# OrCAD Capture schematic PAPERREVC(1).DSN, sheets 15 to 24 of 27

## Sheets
15 PAGE1 (15): size C; title: SNAP, DIGITAL POWER SUPPLIES; block POWER1
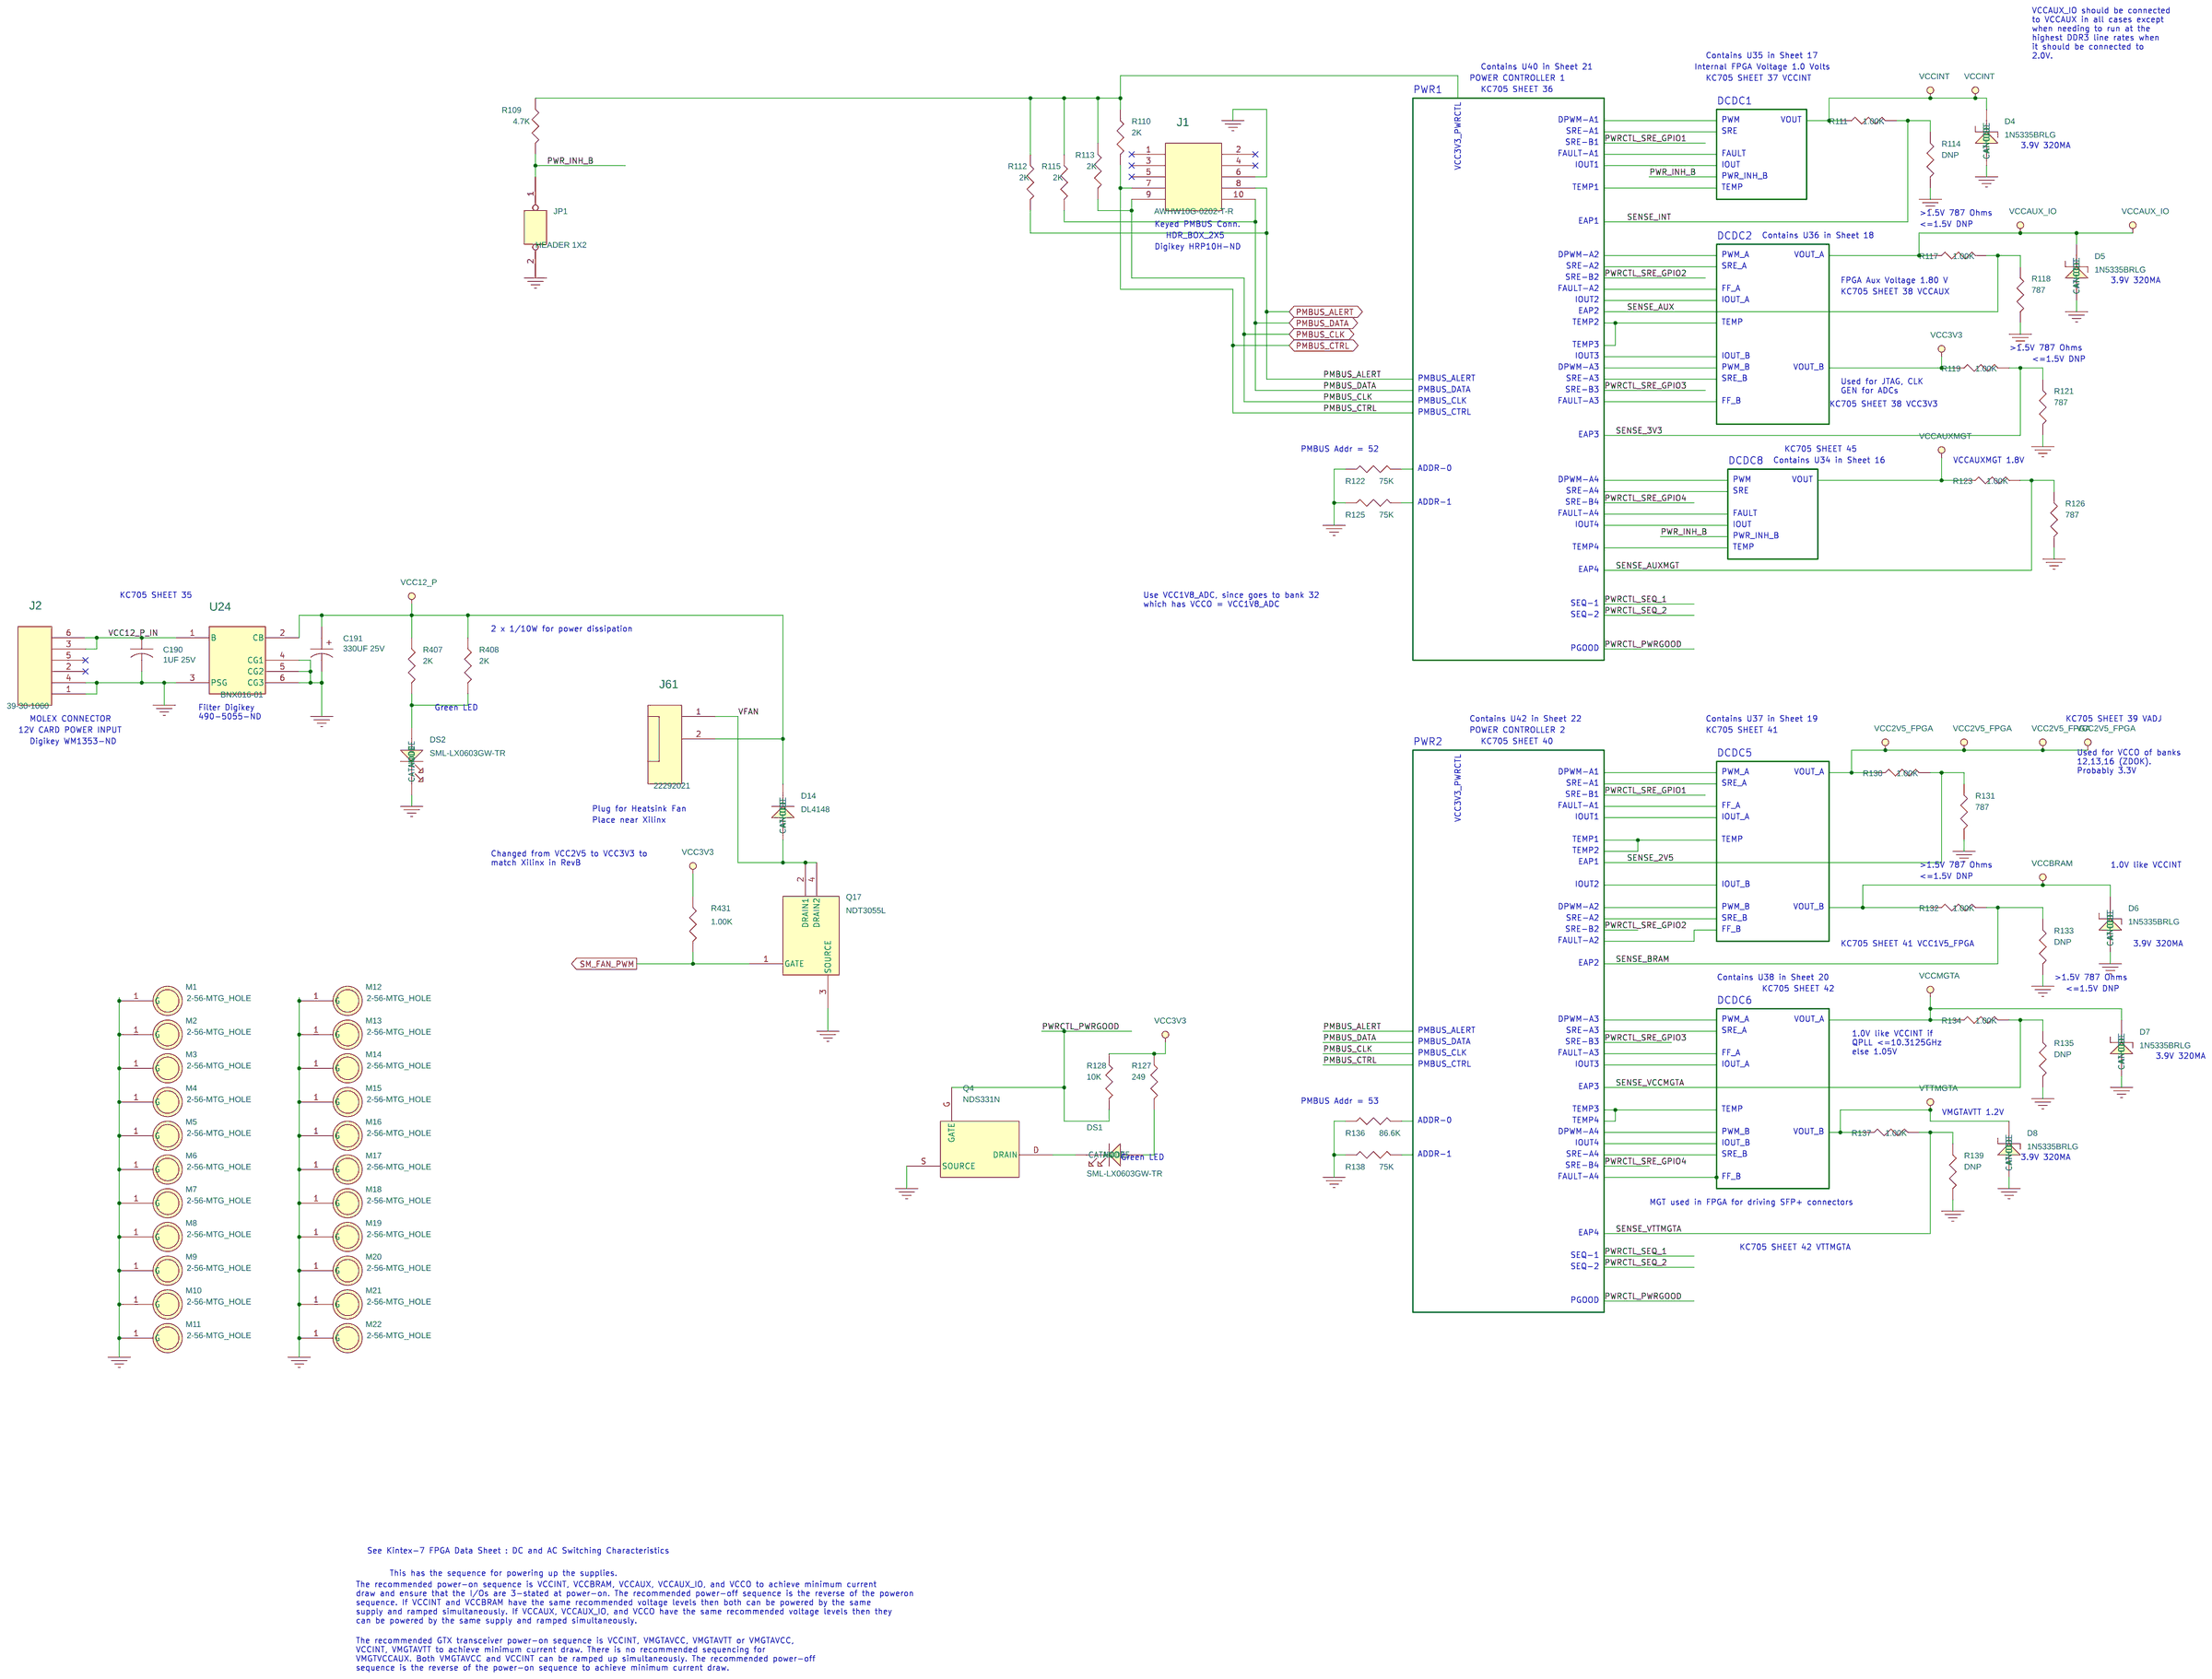
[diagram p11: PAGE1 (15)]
16 PAGE1 (16): size B; title: SNAP, Power1, DCDCx; block POWER1/DCDC6
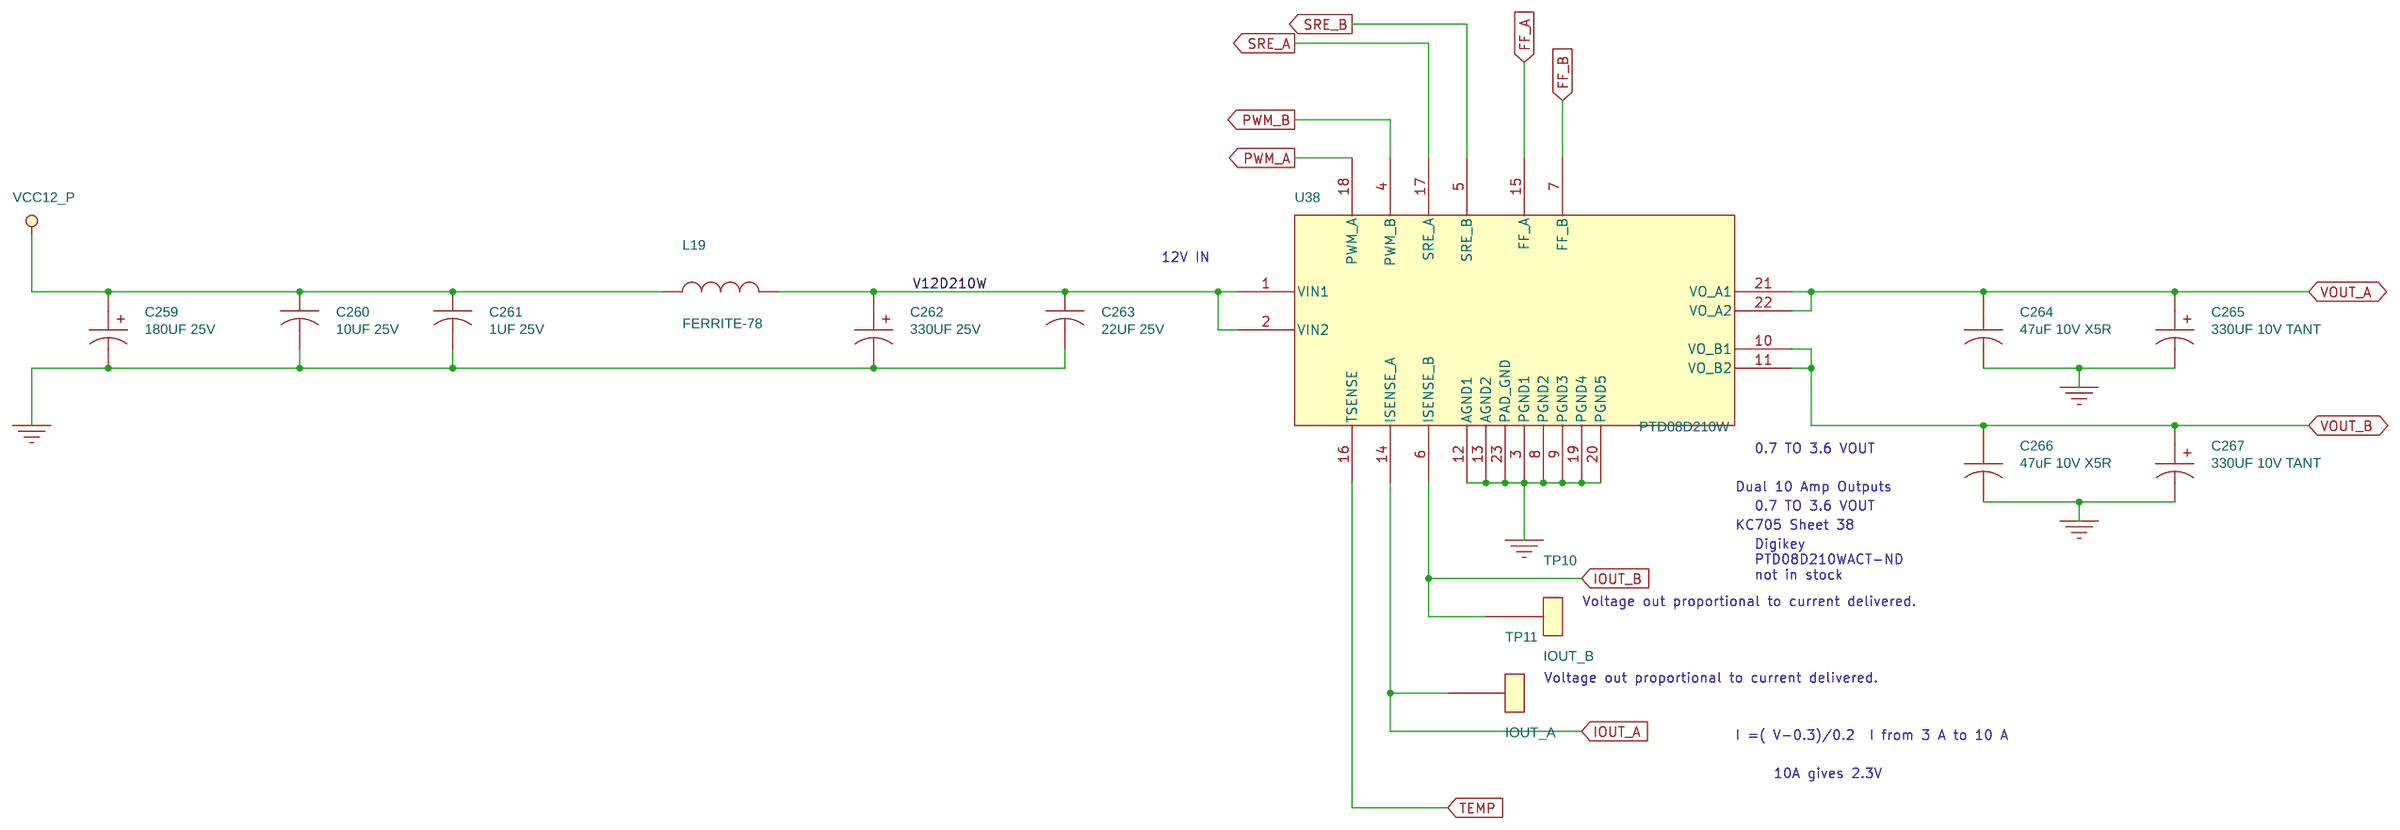
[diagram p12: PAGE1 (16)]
17 PAGE1 (17): size B; title: SNAP, Power1 DCDC1; block POWER1/DCDC1
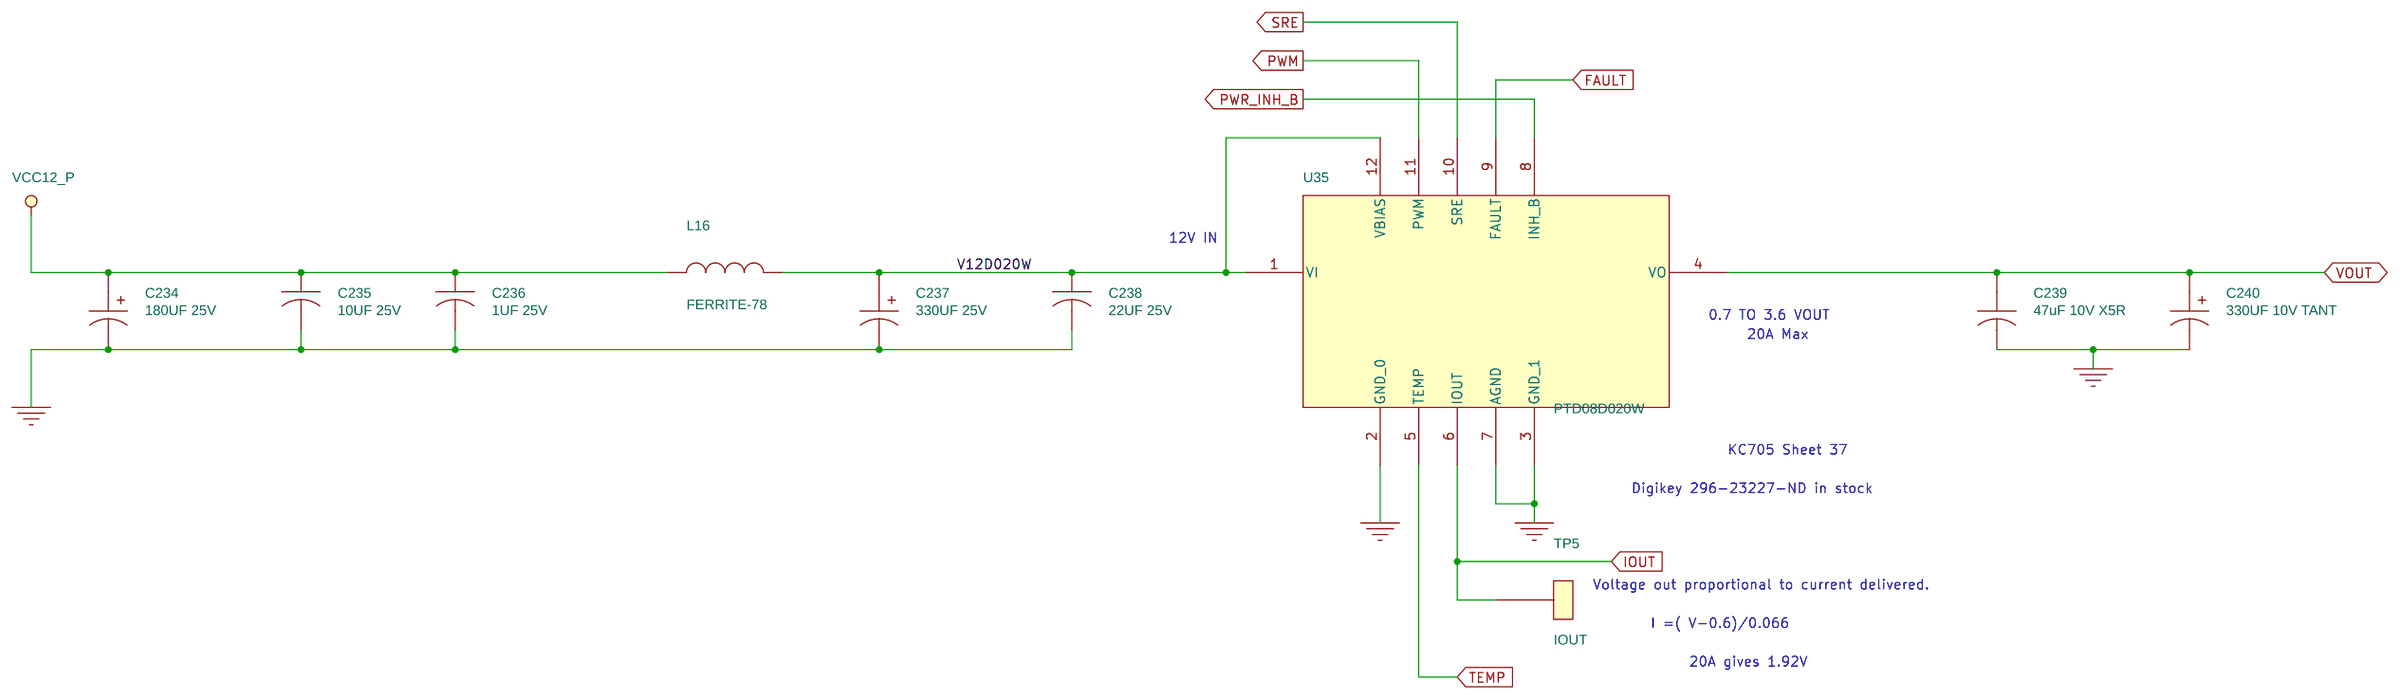
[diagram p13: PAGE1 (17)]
18 PAGE1 (18): block POWER1/DCDC5, another copy of sheet 16
19 PAGE1 (19): size B; title: SNAP, Power1 DCDC8; block POWER1/DCDC8
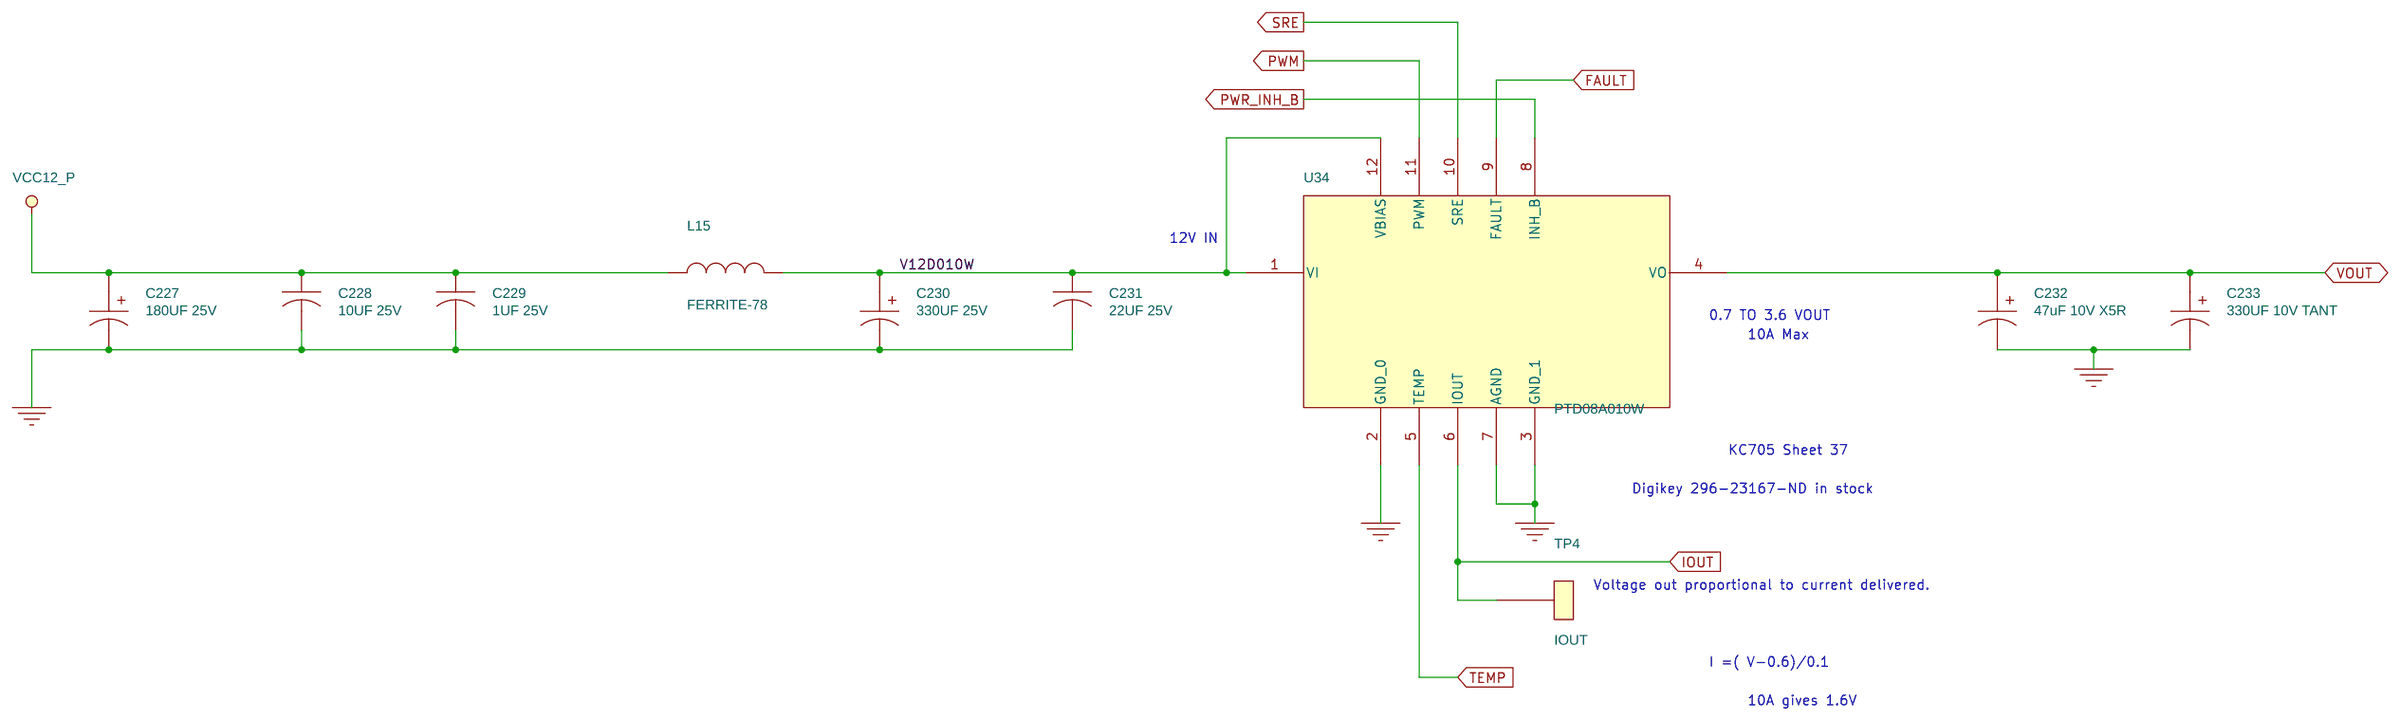
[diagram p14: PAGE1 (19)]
20 PAGE1 (20): size B; title: SNAP, DIGITAL PWM SYSTEM CONTROLLER; block POWER1/PWR1
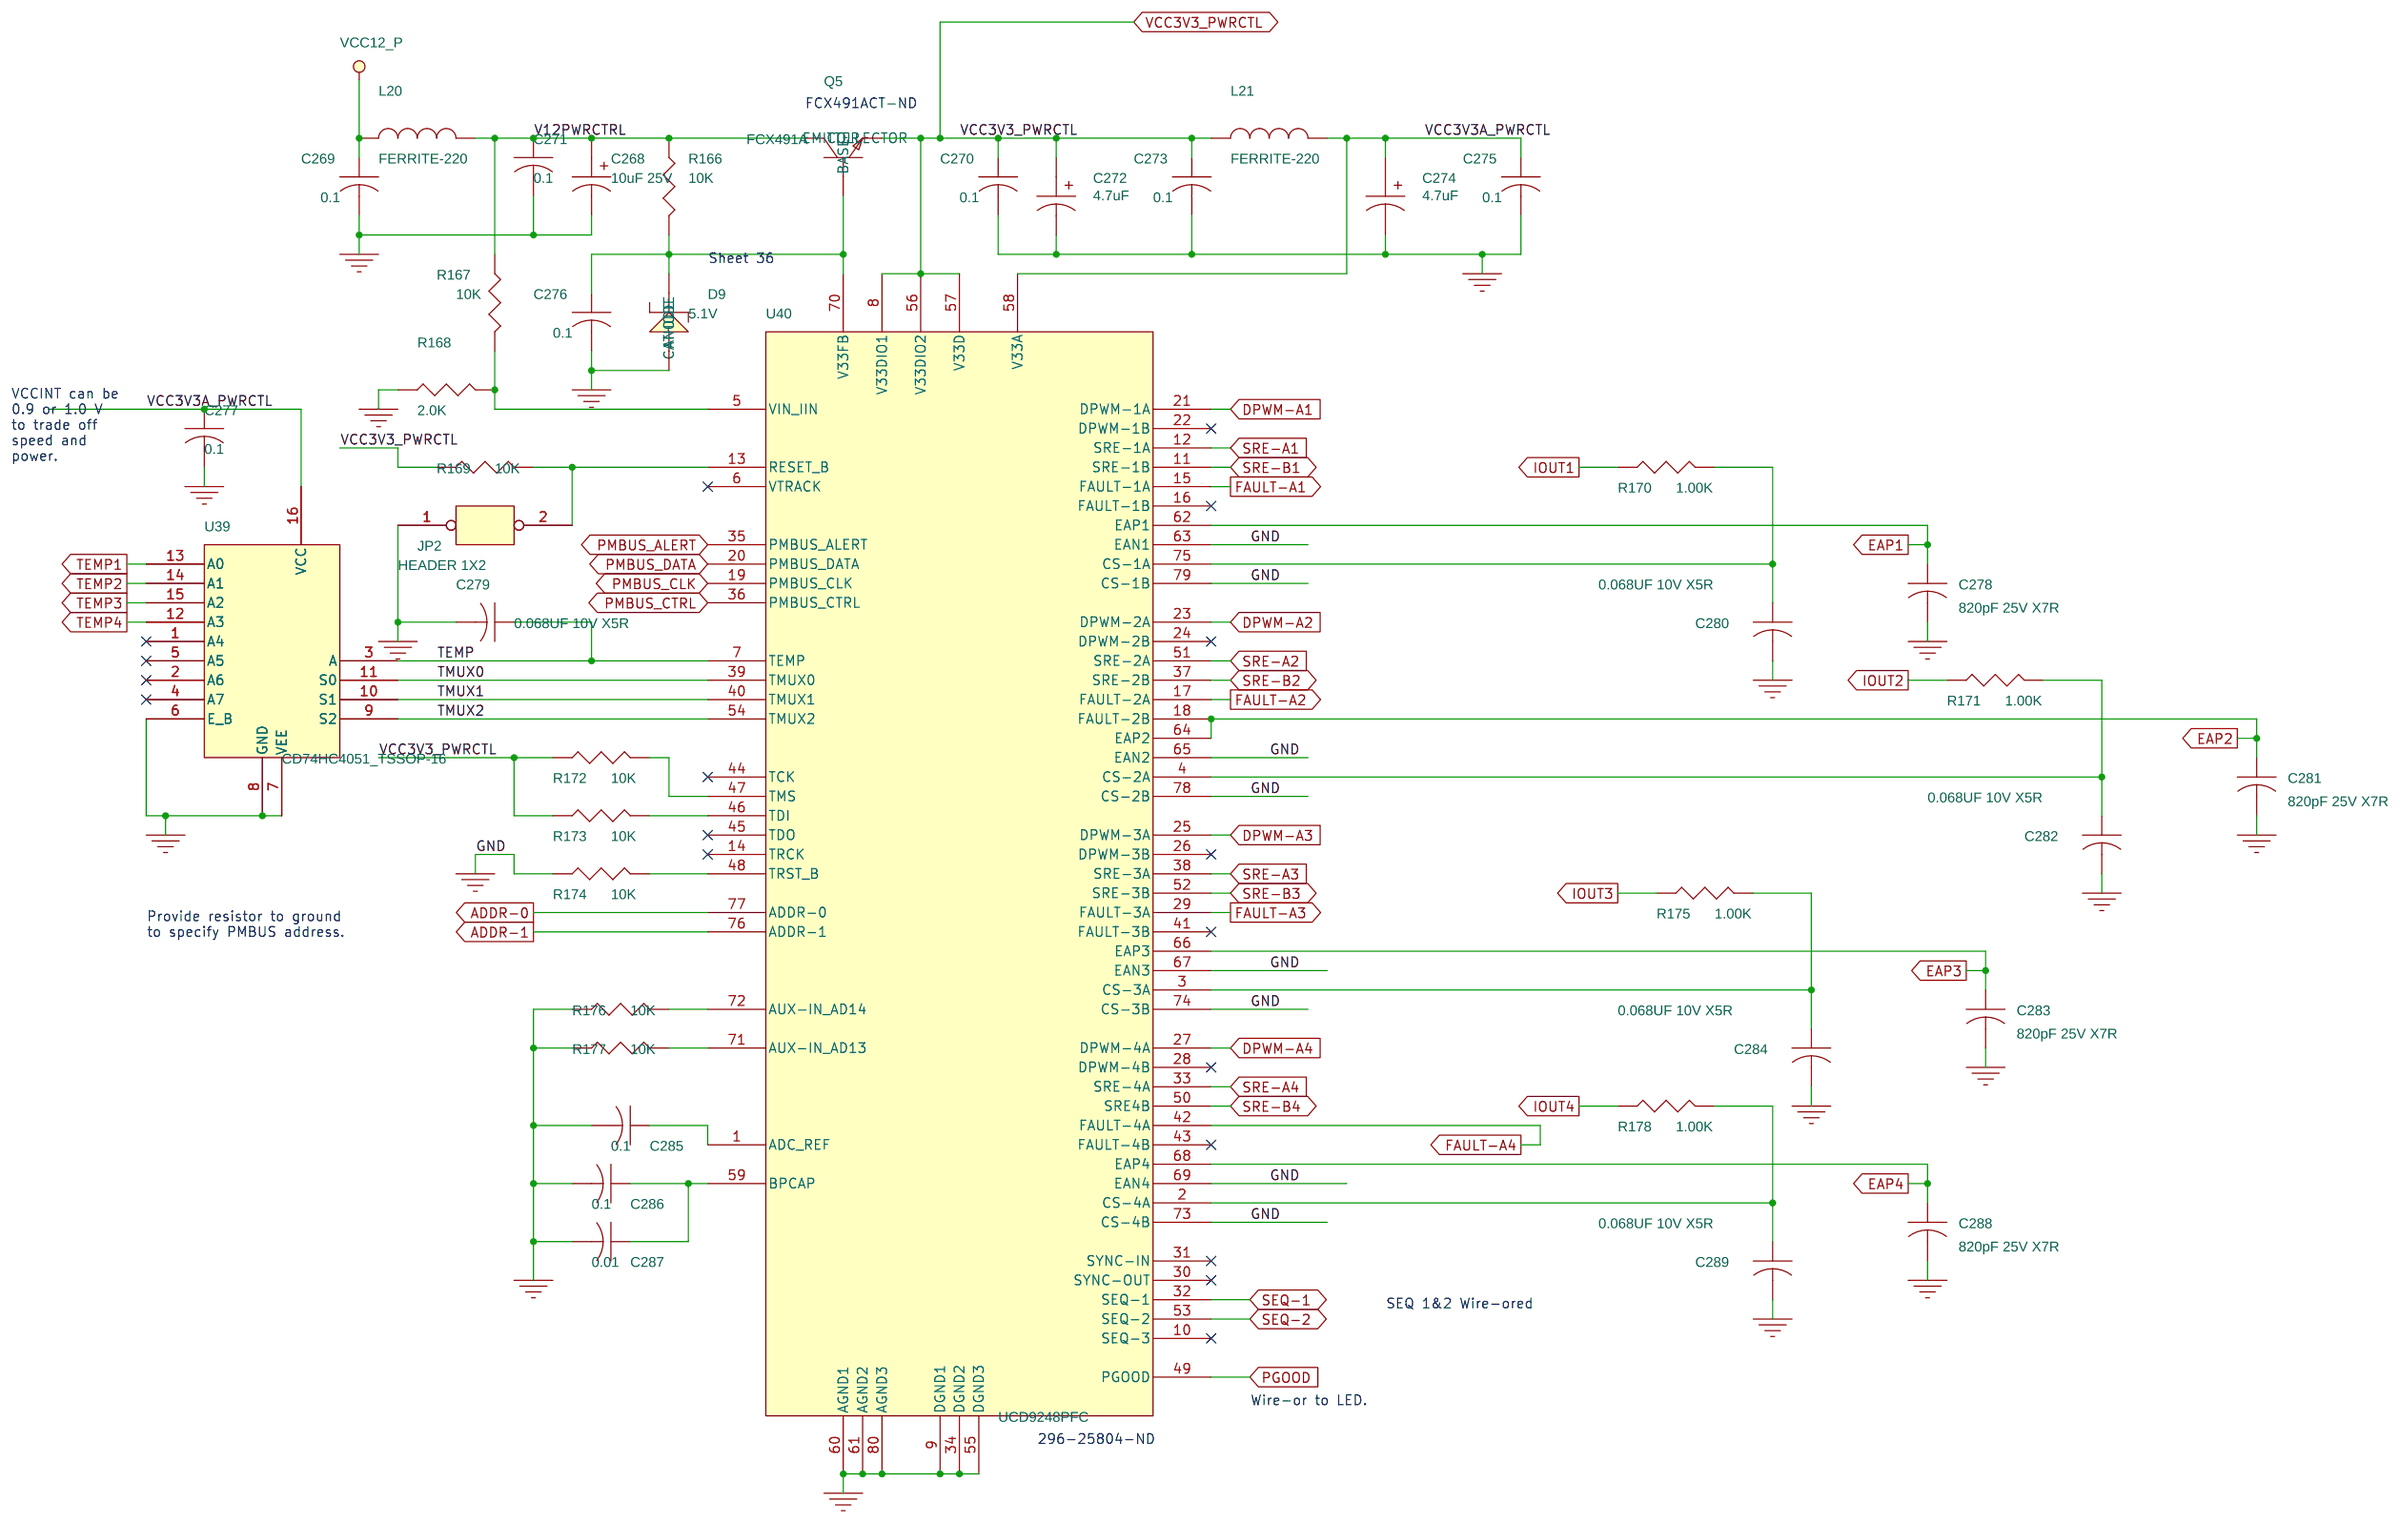
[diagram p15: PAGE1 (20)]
21 PAGE1 (21): block POWER1/PWR2, another copy of sheet 20
22 PAGE1 (22): block POWER1/DCDC2, another copy of sheet 16
23 PAGE1 (23): size B; title: SNAP, Analog Regulators; company: NRAO; block ADCREG
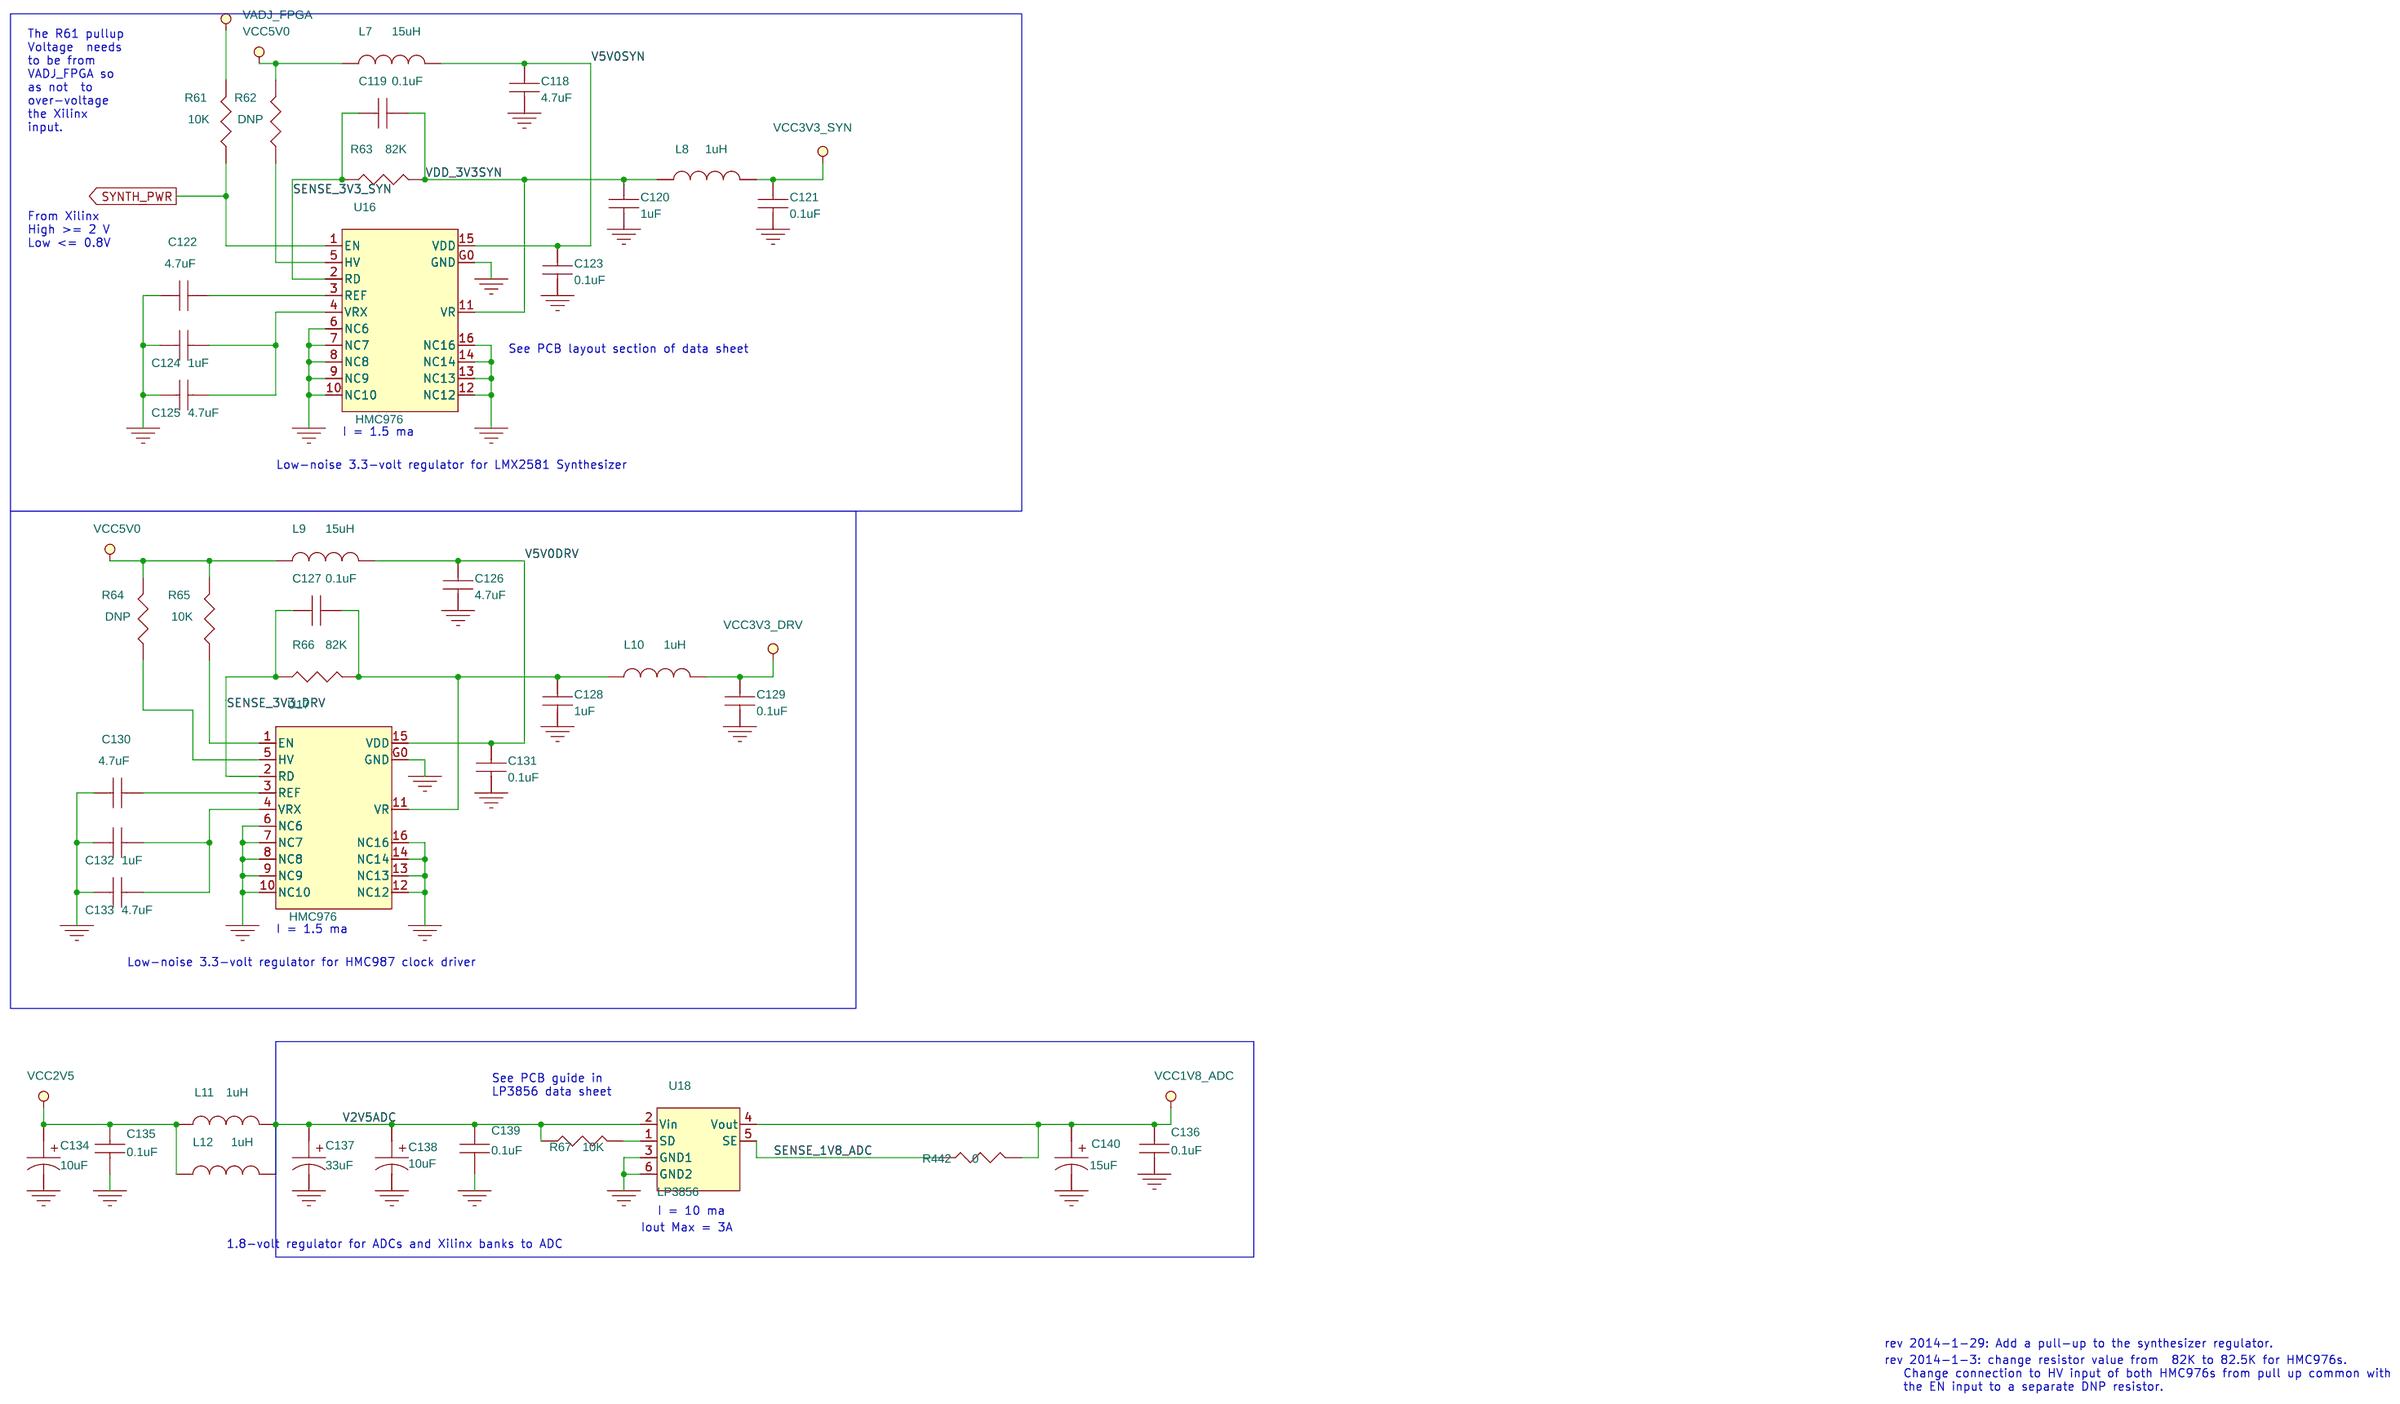
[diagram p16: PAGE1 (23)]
24 PAGE1 (24): size B; title: SNAP, FPGA QSPI; block FPGA14
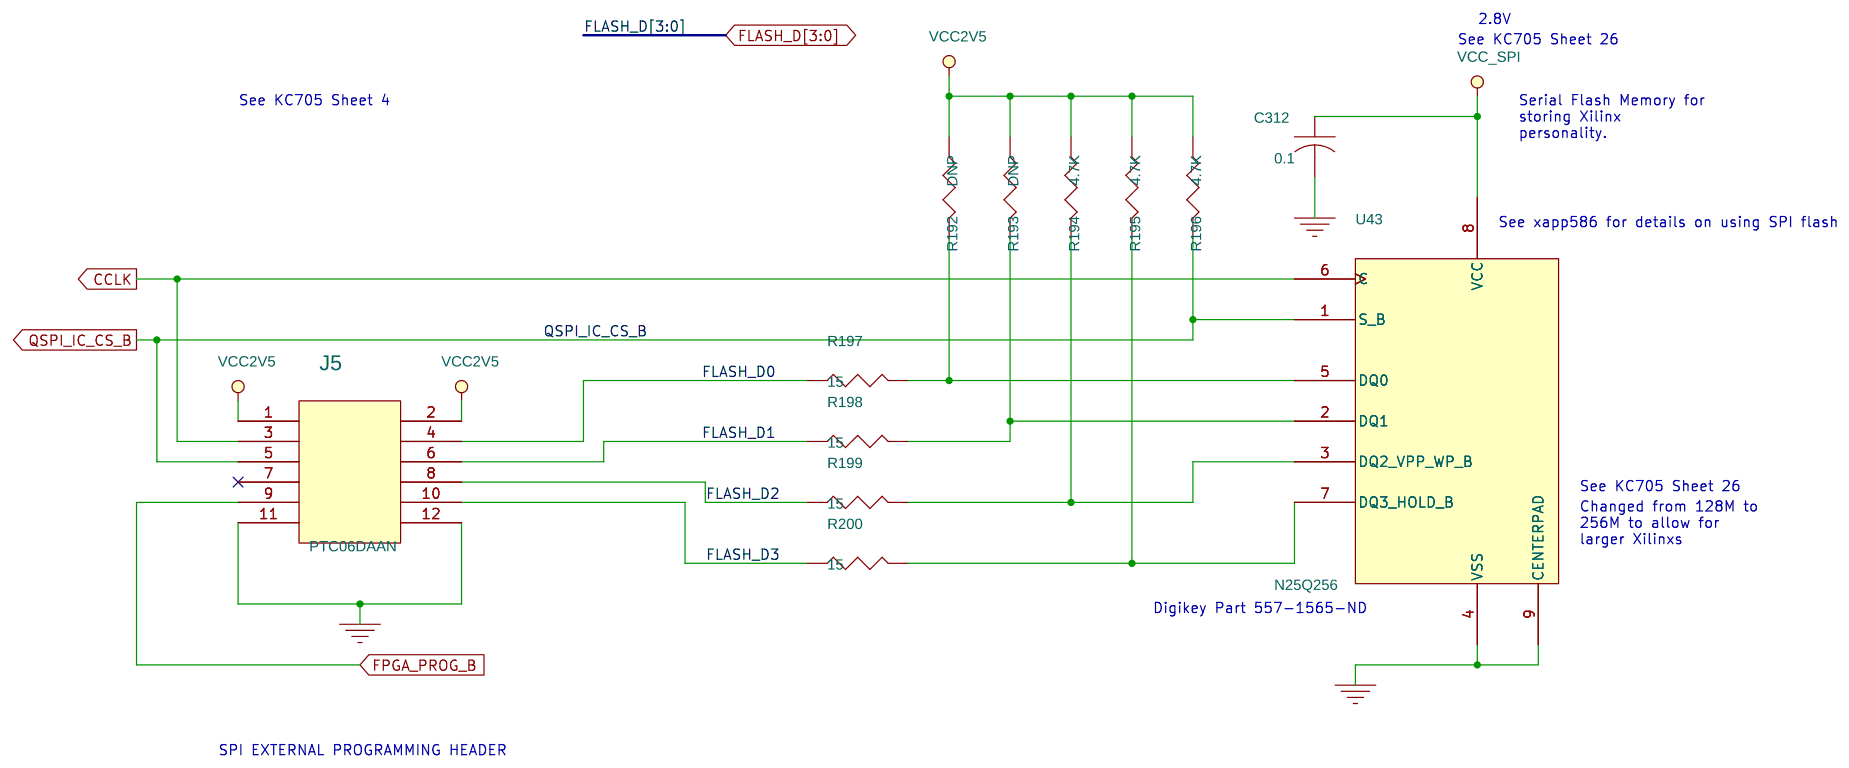
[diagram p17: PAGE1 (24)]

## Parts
sheet PAGE1 (15)
C190  1UF 25V  [CAPC1608X90N]
C191  330UF 25V  [CAPAE830X1050D995DD305L335N]
D4  1N5335BRLG  [DIOAD1365W102L865D350B]
D5  1N5335BRLG  [DIOAD1365W102L865D350B]
D6  1N5335BRLG  [DIOAD1365W102L865D350B]
D7  1N5335BRLG  [DIOAD1365W102L865D350B]
D8  1N5335BRLG  [DIOAD1365W102L865D350B]
D14  DL4148  [DIOMELF3514]
DS1  SML-LX0603GW-TR  [LEDM180X60X60N]
DS2  SML-LX0603GW-TR  [LEDM180X60X60N]
J1  AWHW10G-0202-T-R  [HDRV1016W64P254R2L2032T905H900]
J2  39-30-1060  [MOLEX_39301060]
J61  22292021  [HDR_1x2_LOCK_MOLEX]
JP1  HEADER 1X2  [HDRV254W64P254R1L508T254H838]
M1  2-56-MTG_HOLE  [2-56-MTG_HOLE]
M2  2-56-MTG_HOLE  [2-56-MTG_HOLE]
M3  2-56-MTG_HOLE  [2-56-MTG_HOLE]
M4  2-56-MTG_HOLE  [2-56-MTG_HOLE]
M5  2-56-MTG_HOLE  [2-56-MTG_HOLE]
M6  2-56-MTG_HOLE  [2-56-MTG_HOLE]
M7  2-56-MTG_HOLE  [2-56-MTG_HOLE]
M8  2-56-MTG_HOLE  [2-56-MTG_HOLE]
M9  2-56-MTG_HOLE  [2-56-MTG_HOLE]
M10  2-56-MTG_HOLE  [2-56-MTG_HOLE]
M11  2-56-MTG_HOLE  [2-56-MTG_HOLE]
M12  2-56-MTG_HOLE  [2-56-MTG_HOLE]
M13  2-56-MTG_HOLE  [2-56-MTG_HOLE]
M14  2-56-MTG_HOLE  [2-56-MTG_HOLE]
M15  2-56-MTG_HOLE  [2-56-MTG_HOLE]
M16  2-56-MTG_HOLE  [2-56-MTG_HOLE]
M17  2-56-MTG_HOLE  [2-56-MTG_HOLE]
M18  2-56-MTG_HOLE  [2-56-MTG_HOLE]
M19  2-56-MTG_HOLE  [2-56-MTG_HOLE]
M20  2-56-MTG_HOLE  [2-56-MTG_HOLE]
M21  2-56-MTG_HOLE  [2-56-MTG_HOLE]
M22  2-56-MTG_HOLE  [2-56-MTG_HOLE]
Q4  NDS331N  [SOT95P237X100-4]
Q17  NDT3055L  [SOT230P700x180-4L050N]
R109  4.7K  [RESC1005X35N]
R110  2K  [RESC1005X35N]
R111  1.00K  [RESC1005X35N]
R112  2K  [RESC1005X35N]
R113  2K  [RESC1005X35N]
R114  DNP  [RESC1005X35N]
R115  2K  [RESC1005X35N]
R117  1.00K  [RESC1005X35N]
R118  787  [RESC1005X35N]
R119  1.00K  [RESC1005X35N]
R121  787  [RESC1005X35N]
R122  75K  [RESC1005X35N]
R123  1.00K  [RESC1005X35N]
R125  75K  [RESC1005X35N]
R126  787  [RESC1005X35N]
R127  249  [RESC1005X35N]
R128  10K  [RESC1005X35N]
R130  1.00K  [RESC1005X35N]
R131  787  [RESC1005X35N]
R132  1.00K  [RESC1005X35N]
R133  DNP  [RESC1005X35N]
R134  1.00K  [RESC1005X35N]
R135  DNP  [RESC1005X35N]
R136  86.6K  [RESC1005X35N]
R137  1.00K  [RESC1005X35N]
R138  75K  [RESC1005X35N]
R139  DNP  [RESC1005X35N]
R407  2K  [RESC1005X35N]
R408  2K  [RESC1005X35N]
R431  1.00K  [RESC1005X35N]
U24  BNX016-01  [FIL_BNX01x]
sheet PAGE1 (16)
C259  180UF 25V  [CAPPRD350W60D820H1170P]
C260  10UF 25V  [CAPC3216X180N]
C261  1UF 25V  [CAPC1608X90N]
C262  330UF 25V  [CAPAE830X1050D995DD305L335N]
C263  22UF 25V  [CAPC3216X180N]
C264  47uF 10V X5R  [CAPC3216X180N]
C265  330UF 10V TANT  [CAPMP7343X310N-ALT1]
C266  47uF 10V X5R  [CAPC3216X180N]
C267  330UF 10V TANT  [CAPMP7343X310N-ALT1]
L19  FERRITE-78  [INDM9630X305N]
TP10  IOUT_B  [TP107]
TP11  IOUT_A  [TP107]
U38  PTD08D210W  [DCDC-CONV_PTD08D210W-22N]
sheet PAGE1 (17)
C234  180UF 25V  [CAPPRD350W60D820H1170P]
C235  10UF 25V  [CAPC3216X180N]
C236  1UF 25V  [CAPC1608X90N]
C237  330UF 25V  [CAPAE830X1050D995DD305L335N]
C238  22UF 25V  [CAPC3216X180N]
C239  47uF 10V X5R  [CAPC3216X180N]
C240  330UF 10V TANT  [CAPMP7343X310N-ALT1]
L16  FERRITE-78  [INDM9630X305N]
TP5  IOUT  [TP107]
U35  PTD08D020W  [DCDC-CONV_PTD08A020WAD-12N]
sheet PAGE1 (18)
C250  180UF 25V  [CAPPRD350W60D820H1170P]
C251  10UF 25V  [CAPC3216X180N]
C252  1UF 25V  [CAPC1608X90N]
C253  330UF 25V  [CAPAE830X1050D995DD305L335N]
C254  22UF 25V  [CAPC3216X180N]
C255  47uF 10V X5R  [CAPC3216X180N]
C256  330UF 10V TANT  [CAPMP7343X310N-ALT1]
C257  47uF 10V X5R  [CAPC3216X180N]
C258  330UF 10V TANT  [CAPMP7343X310N-ALT1]
L18  FERRITE-78  [INDM9630X305N]
TP8  IOUT_B  [TP107]
TP9  IOUT_A  [TP107]
U37  PTD08D210W  [DCDC-CONV_PTD08D210W-22N]
sheet PAGE1 (19)
C227  180UF 25V  [CAPPRD350W60D820H1170P]
C228  10UF 25V  [CAPC3216X180N]
C229  1UF 25V  [CAPC1608X90N]
C230  330UF 25V  [CAPAE830X1050D995DD305L335N]
C231  22UF 25V  [CAPC3216X180N]
C232  47uF 10V X5R  [CAPC3216X180N]
C233  330UF 10V TANT  [CAPMP7343X310N-ALT1]
L15  FERRITE-78  [INDM9630X305N]
TP4  IOUT  [TP107]
U34  PTD08A010W  [DCDC-CONV_PTD08A010WAD-12N]
sheet PAGE1 (20)
C268  10uF 25V  [CAPC3216X180N]
C269  0.1  [CAPC1005X50L]
C270  0.1  [CAPC1005X50L]
C271  0.1  [CAPC1005X50L]
C272  4.7uF  [CAPC2012X140N]
C273  0.1  [CAPC1005X50L]
C274  4.7uF  [CAPC2012X140N]
C275  0.1  [CAPC1005X50L]
C276  0.1  [CAPC1005X50L]
C277  0.1  [CAPC1005X50L]
C278  820pF 25V X7R  [CAPC0603X30L]
C279  0.068UF 10V X5R  [CAPC1005X50L]
C280  0.068UF 10V X5R  [CAPC1005X50L]
C281  820pF 25V X7R  [CAPC0603X30L]
C282  0.068UF 10V X5R  [CAPC1005X50L]
C283  820pF 25V X7R  [CAPC0603X30L]
C284  0.068UF 10V X5R  [CAPC1005X50L]
C285  0.1  [CAPC1005X50L]
C286  0.1  [CAPC1005X50L]
C287  0.01  [CAPC1005X50L]
C288  820pF 25V X7R  [CAPC0603X30L]
C289  0.068UF 10V X5R  [CAPC1005X50L]
D9  5.1V  [SOD3717X135]
JP2  HEADER 1X2  [HDRV254W64P254R1L508T254H838]
L20  FERRITE-220  [INDC1608X95L-ALT1]
L21  FERRITE-220  [INDC1608X95L-ALT1]
Q5  FCX491A  [SOT89]
R166  10K  [RESC1005X35N]
R167  10K  [RESC1005X35N]
R168  2.0K  [RESC1005X35N]
R169  10K  [RESC1005X35N]
R170  1.00K  [RESC1005X35N]
R171  1.00K  [RESC1005X35N]
R172  10K  [RESC1005X35N]
R173  10K  [RESC1005X35N]
R174  10K  [RESC1005X35N]
R175  1.00K  [RESC1005X35N]
R176  10K  [RESC1005X35N]
R177  10K  [RESC1005X35N]
R178  1.00K  [RESC1005X35N]
U39  CD74HC4051_TSSOP-16  [SOP65P640X120-16N]
U40  UCD9248PFC  [QFP50P1400X1400X100-80N]
sheet PAGE1 (21)
C290  10uF 25V  [CAPC3216X180N]
C291  0.1  [CAPC1005X50L]
C292  0.1  [CAPC1005X50L]
C293  0.1  [CAPC1005X50L]
C294  4.7uF  [CAPC2012X140N]
C295  0.1  [CAPC1005X50L]
C296  4.7uF  [CAPC2012X140N]
C297  0.1  [CAPC1005X50L]
C298  0.1  [CAPC1005X50L]
C299  0.1  [CAPC1005X50L]
C300  820pF 25V X7R  [CAPC0603X30L]
C301  0.068UF 10V X5R  [CAPC1005X50L]
C302  0.068UF 10V X5R  [CAPC1005X50L]
C303  820pF 25V X7R  [CAPC0603X30L]
C304  0.068UF 10V X5R  [CAPC1005X50L]
C305  820pF 25V X7R  [CAPC0603X30L]
C306  0.068UF 10V X5R  [CAPC1005X50L]
C307  0.1  [CAPC1005X50L]
C308  0.1  [CAPC1005X50L]
C309  0.01  [CAPC1005X50L]
C310  820pF 25V X7R  [CAPC0603X30L]
C311  0.068UF 10V X5R  [CAPC1005X50L]
D10  5.1V  [SOD3717X135]
JP3  HEADER 1X2  [HDRV254W64P254R1L508T254H838]
L22  FERRITE-220  [INDC1608X95L-ALT1]
L23  FERRITE-220  [INDC1608X95L-ALT1]
Q6  FCX491A  [SOT89]
R179  10K  [RESC1005X35N]
R180  10K  [RESC1005X35N]
R181  2.0K  [RESC1005X35N]
R182  10K  [RESC1005X35N]
R183  1.00K  [RESC1005X35N]
R184  1.00K  [RESC1005X35N]
R185  10K  [RESC1005X35N]
R186  10K  [RESC1005X35N]
R187  10K  [RESC1005X35N]
R188  1.00K  [RESC1005X35N]
R189  10K  [RESC1005X35N]
R190  10K  [RESC1005X35N]
R191  1.00K  [RESC1005X35N]
U41  CD74HC4051_TSSOP-16  [SOP65P640X120-16N]
U42  UCD9248PFC  [QFP50P1400X1400X100-80N]
sheet PAGE1 (22)
C241  180UF 25V  [CAPPRD350W60D820H1170P]
C242  10UF 25V  [CAPC3216X180N]
C243  1UF 25V  [CAPC1608X90N]
C244  330UF 25V  [CAPAE830X1050D995DD305L335N]
C245  22UF 25V  [CAPC3216X180N]
C246  47uF 10V X5R  [CAPC3216X180N]
C247  330UF 10V TANT  [CAPMP7343X310N-ALT1]
C248  47uF 10V X5R  [CAPC3216X180N]
C249  330UF 10V TANT  [CAPMP7343X310N-ALT1]
L17  FERRITE-78  [INDM9630X305N]
TP6  IOUT_B  [TP107]
TP7  IOUT_A  [TP107]
U36  PTD08D210W  [DCDC-CONV_PTD08D210W-22N]
sheet PAGE1 (23)
C118  4.7uF  [CAPC2012X140N]
C119  0.1uF  [CAPC1005X50L]
C120  1uF  [CAPC1608X90N]
C121  0.1uF  [CAPC1005X50L]
C122  4.7uF  [CAPC2012X140N]
C123  0.1uF  [CAPC1005X50L]
C124  1uF  [CAPC1608X90N]
C125  4.7uF  [CAPC2012X140N]
C126  4.7uF  [CAPC2012X140N]
C127  0.1uF  [CAPC1005X50L]
C128  1uF  [CAPC1608X90N]
C129  0.1uF  [CAPC1005X50L]
C130  4.7uF  [CAPC2012X140N]
C131  0.1uF  [CAPC1005X50L]
C132  1uF  [CAPC1608X90N]
C133  4.7uF  [CAPC2012X140N]
C134  10uF  [CAPC3216X180N]
C135  0.1uF  [CAPC1005X50L]
C136  0.1uF  [CAPC1005X50L]
C137  33uF  [CAPMP7343X310N-ALT1]
C138  10uF  [CAPC3216X180N]
C139  0.1uF  [CAPC1005X50L]
C140  15uF  [CAPC1608X90N]
L7  15uH  [INDM4532X340N]
L8  1uH  [INDM4532X340N]
L9  15uH  [INDM4532X340N]
L10  1uH  [INDM4532X340N]
L11  1uH  [INDM4532X340N]
L12  1uH  [INDM4532X340N]
R61  10K  [RESC1005X35N]
R62  DNP  [RESC1005X35N]
R63  82K  [RESC1005X35N]
R64  DNP  [RESC1005X35N]
R65  10K  [RESC1005X35N]
R66  82K  [RESC1005X35N]
R67  10K  [RESC1005X35N]
R442  0  [RESC1005X35N]
U16  HMC976  [QFN50P300X300X100-17T178X178L]
U17  HMC976  [QFN50P300X300X100-17T178X178L]
U18  LP3856  [TO170P1430X470-6N-ALT1]
sheet PAGE1 (24)
C312  0.1  [CAPC1005X50L]
J5  PTC06DAAN  [HDRV6X2]
R192  DNP  [RESC1608X50N]
R193  DNP  [RESC1608X50N]
R194  4.7K  [RESC1005X35N]
R195  4.7K  [RESC1005X35N]
R196  4.7K  [RESC1005X35N]
R197  15  [RESC1005X35N]
R198  15  [RESC1005X35N]
R199  15  [RESC1005X35N]
R200  15  [RESC1005X35N]
U43  N25Q256  [DFN127P600X800X100-9T526X490N]

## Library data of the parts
C190 C228 C229 C231 C235 C236 C238 C242 C243 C245 C251 C252 C254 C260 C261 C263 C269-C271 C273 C275-C289 C291-C293 C295 C297-C312 = CAP_0
C191 C227 C230 C232-C234 C237 C240 C241 C244 C247 C249 C250 C253 C256 C258 C259 C262 C265 C267 C272 C274 C294 C296 = CAPACITOR_POL_0
D4-D8 = DIODE_ZENER_1
D14 = DIODE_0
DS1 = LED_3
DS2 = LED_2
J1 = HEADER_6x2_SM_14: COMPHEIGHT: 0.000; DECOUPLER: NO; MEMORY: NO
J2 = HEADER_6x2_SM_15: COMPHEIGHT: 0.000; DECOUPLER: NO; MEMORY: NO
J61 = HEADER_6x2_SM_21: COMPHEIGHT: 0.000; DECOUPLER: NO; MEMORY: NO
JP1 = HEADER_2X2_3
M1-M22 = 2-56-MTG-HOLE_0: Designator: <Designator>
Q4 = XC17256L_14
Q17 = XC17256L_30
R109 R114 R118 R121 R122 R125-R128 R131 R133 R135 R136 R138 R139 R166-R191 R431 = RESISTOR_0: COMPHEIGHT: 0.000; DECOUPLER: NO; MEMORY: NO; POWER: 1/10W; PRECISION: 1%
R110-R113 R115 R117 R119 R123 R130 R132 R134 R137 R407 R408 R442 = RESISTOR_0: COMPHEIGHT: 0.000; DECOUPLER: NO; MEMORY: NO; POWER: 1/16W; PRECISION: 1%
U24 = HEADER_6x2_SM_18: COMPHEIGHT: 0.000; DECOUPLER: NO; MEMORY: NO
C246 C255 C264 = CAPACITOR_POL_4
C248 C257 C266 = CAPACITOR_POL_5
L15-L23 = INDUCTOR_0
TP4-TP11 = TEST_POINT
U36-U38 = 1_2_BRICK_23: COMPFIXED: NO; COMPGROUP: 0; COMPHEIGHT: 0.000; COMPKEY: NO; COMPLOC: [9600.000,-13400.000]; COMPLOCKED: NO; COMPROT: 0; COMPSIDE: TOP; DECOUPLER: NO; MEMORY: NO
C239 = CAPACITOR_POL_3
U35 = 1_2_BRICK_24: COMPFIXED: NO; COMPGROUP: 0; COMPHEIGHT: 0.000; COMPKEY: NO; COMPLOC: [9600.000,-13400.000]; COMPLOCKED: NO; COMPROT: 0; COMPSIDE: TOP; DECOUPLER: NO; MEMORY: NO
U34 = 1_2_BRICK_25: COMPFIXED: NO; COMPGROUP: 0; COMPHEIGHT: 0.000; COMPKEY: NO; COMPLOC: [9600.000,-13400.000]; COMPLOCKED: NO; COMPROT: 0; COMPSIDE: TOP; DECOUPLER: NO; MEMORY: NO
C268 C290 = CAPACITOR_POL_0: Voltage: 25V
D9 D10 = DIODE_ZENER_0
JP2 JP3 = HEADER_2X2_4
Q5 Q6 = NPN_0
U39 U41 = 1_2_BRICK_10: COMPFIXED: NO; COMPGROUP: 0; COMPHEIGHT: 0.000; COMPKEY: NO; COMPLOC: [9600.000,-13400.000]; COMPLOCKED: NO; COMPROT: 0; COMPSIDE: TOP; DECOUPLER: NO; MEMORY: NO
U40 U42 = 1_2_BRICK_26: COMPFIXED: NO; COMPGROUP: 0; COMPHEIGHT: 0.000; COMPKEY: NO; COMPLOC: [9600.000,-13400.000]; COMPLOCKED: NO; COMPROT: 0; COMPSIDE: TOP; DECOUPLER: NO; MEMORY: NO
C118 C122 C125 C126 C130 C133 = CAP_NP: Size: 0805; Temp. Coef.: X5R; Tolerance: 10%; Voltage Rating: 10V
C119 C127 C135 C139 = CAP_NP: Size: 0402; Temp. Coef.: X5R; Tolerance: 10%; Voltage Rating: 10V
C120 C124 C128 C132 = CAP_NP: Size: 0603; Temp. Coef.: X5R; Tolerance: 10%; Voltage Rating: 10V
C121 C123 C129 C131 = CAP_NP: Size: 0402; Temp. Coef.: X5R; Tolerance: 10%; Voltage Rating: 10 V
C134 C137 C138 C140 = CAP_POL: ESR: < 2 Ohms; Tolerance: 10 %
C136 = CAP_NP
L7 L9 = INDUCTOR: Current Rating: 0.45 A; DC Resistance: 0.7 ohms; Digikey P/N: NLC453232T-1R0K-PF; Size: 1812; Tolerance: 10%
L8 L10 = INDUCTOR: Current Rating: 1.05 A; DC Resistance: 0.11 ohms; Digikey P/N: NLC453232T-1R0K-PF; Size: 1812; Tolerance: 10%
L11 L12 = INDUCTOR
R61 R62 R64 R65 R67 = RESISTOR_SM: Power Rating: 1/16 W; Size: 0402; Tolerance: 5%
R63 R66 = RESISTOR_SM: Power Rating: 1/16 W; Size: 0402; Temp. Coef.: 50 ppm; Tolerance: 1%
U16 U17 = HMC976
U18 = LP3856_0
J5 = HEADER_6x2_SM_16: COMPHEIGHT: 0.000; DECOUPLER: NO; MEMORY: NO
R192-R196 = RESISTOR_0: COMPHEIGHT: 0.000; DECOUPLER: NO; MEMORY: NO; PRECISION: 5%
R197-R200 = RESISTOR_0: COMPHEIGHT: 0.000; DECOUPLER: NO; MEMORY: NO; PRECISION: 1%
U43 = XC17256L_28

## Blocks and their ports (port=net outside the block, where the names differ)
POWER1/DCDC6 = schematic PTD08D210W, on sheet PAGE1: FF_A=POWER1/N9976400, TEMP=POWER1/N9979651, FF_B=POWER1/N9976212, SRE_A=POWER1/N9976392, PWM_A=POWER1/N9976388, SRE_B=POWER1/N10027193, PWM_B=POWER1/N9976204, VOUT_A=VCCMGTA, VOUT_B=VTTMGTA, IOUT_A=POWER1/N10025114, IOUT_B=POWER1/N10025413
POWER1/PWR1 = schematic PWRCTRL, on sheet PAGE1: PGOOD=POWER1/PWRCTL_PWRGOOD, SEQ-1=POWER1/PWRCTL_SEQ_1, SEQ-2=POWER1/PWRCTL_SEQ_2, DPWM-A1=POWER1/N9957217, DPWM-A2=POWER1/N9961675, DPWM-A3=POWER1/N9961716, DPWM-A4=POWER1/N9981203, SRE-A1=POWER1/N9957233, SRE-A2=POWER1/N9961687, SRE-A3=POWER1/N9961728, SRE-A4=POWER1/N9981207, SRE-B1=POWER1/PWRCTL_SRE_GPIO1, SRE-B2=POWER1/PWRCTL_SRE_GPIO2, SRE-B3=POWER1/PWRCTL_SRE_GPIO3, SRE-B4=POWER1/PWRCTL_SRE_GPIO4, FAULT-A1=POWER1/N9957245, FAULT-A2=POWER1/N9961756, FAULT-A3=POWER1/N9961785, FAULT-A4=POWER1/N9981215, EAP1=POWER1/SENSE_INT, EAP2=POWER1/SENSE_AUX, EAP3=POWER1/SENSE_3V3, EAP4=POWER1/SENSE_AUXMGT, TEMP4=POWER1/N9981383, TEMP1=POWER1/N9957257, TEMP2=POWER1/N9961809, TEMP3=POWER1/N9961809, PMBUS_ALERT=N9967336, PMBUS_DATA=N9967310, PMBUS_CLK=N9967323, PMBUS_CTRL=N9967512, ADDR-0=POWER1/N9950688, ADDR-1=POWER1/N9950692, VCC3V3_PWRCTL=POWER1/N9953338, IOUT1=POWER1/N10023674, IOUT2=POWER1/N10023686, IOUT3=POWER1/N10023698, IOUT4=POWER1/N10026393
POWER1/DCDC2 = schematic PTD08D210W, on sheet PAGE1: FF_A=POWER1/N9961756, TEMP=POWER1/N9961809, FF_B=POWER1/N9961785, SRE_A=POWER1/N9961687, PWM_A=POWER1/N9961675, SRE_B=POWER1/N9961728, PWM_B=POWER1/N9961716, VOUT_A=VCCAUX, VOUT_B=VCC3V3, IOUT_A=POWER1/N10023686, IOUT_B=POWER1/N10023698
POWER1/DCDC8 = schematic PTD08A010W, on sheet PAGE1: SRE=POWER1/N9981207, PWM=POWER1/N9981203, TEMP=POWER1/N9981383, VOUT=VCCAUXMGT, FAULT=POWER1/N9981215, PWR_INH_B=POWER1/PWR_INH_B, IOUT=POWER1/N10026393
POWER1/PWR2 = schematic PWRCTRL, on sheet PAGE1: PGOOD=POWER1/PWRCTL_PWRGOOD, SEQ-1=POWER1/PWRCTL_SEQ_1, SEQ-2=POWER1/PWRCTL_SEQ_2, DPWM-A1=POWER1/N9976038, DPWM-A2=POWER1/N9976380, DPWM-A3=POWER1/N9976388, DPWM-A4=POWER1/N9976204, SRE-A1=POWER1/N9976042, SRE-A2=POWER1/N9976384, SRE-A3=POWER1/N9976392, SRE-A4=POWER1/N10027193, SRE-B1=POWER1/PWRCTL_SRE_GPIO1, SRE-B2=POWER1/PWRCTL_SRE_GPIO2, SRE-B3=POWER1/PWRCTL_SRE_GPIO3, SRE-B4=POWER1/PWRCTL_SRE_GPIO4, FAULT-A1=POWER1/N9976046, FAULT-A2=POWER1/N9976396, FAULT-A3=POWER1/N9976400, FAULT-A4=POWER1/N9976212, EAP1=POWER1/SENSE_2V5, EAP2=POWER1/SENSE_BRAM, EAP3=POWER1/SENSE_VCCMGTA, EAP4=POWER1/SENSE_VTTMGTA, TEMP4=POWER1/N9979651, TEMP1=POWER1/N9976050, TEMP2=POWER1/N9976050, TEMP3=POWER1/N9979651, PMBUS_ALERT=N9967336, PMBUS_DATA=N9967310, PMBUS_CLK=N9967323, PMBUS_CTRL=N9967512, ADDR-0=POWER1/N9976678, ADDR-1=POWER1/N9976682, VCC3V3_PWRCTL=open, IOUT1=POWER1/N10024540, IOUT2=POWER1/N10024867, IOUT3=POWER1/N10025114, IOUT4=POWER1/N10025413
POWER1/DCDC5 = schematic PTD08D210W, on sheet PAGE1: FF_A=POWER1/N9976046, TEMP=POWER1/N9976050, FF_B=POWER1/N9976396, SRE_A=POWER1/N9976042, PWM_A=POWER1/N9976038, SRE_B=POWER1/N9976384, PWM_B=POWER1/N9976380, VOUT_A=VADJ, VOUT_B=VCCBRAM, IOUT_A=POWER1/N10024540, IOUT_B=POWER1/N10024867
POWER1/DCDC1 = schematic PTD08D020W, on sheet PAGE1: SRE=POWER1/N9957233, PWM=POWER1/N9957217, TEMP=POWER1/N9957257, VOUT=VCCINT, FAULT=POWER1/N9957245, PWR_INH_B=POWER1/PWR_INH_B, IOUT=POWER1/N10023674

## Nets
ADCREG/V2V5ADC: C137.1 C138.1 C139.1 L11.2 L12.2 R67.1 U18.2(Vin)
ADCREG/V5V0DRV: C126.1 C131.1 L9.2 U17.15(VDD)
ADCREG/V5V0SYN: C118.1 C123.1 L7.2 U16.15(VDD)
ADCREG/VDD_3V3SYN: C119.2 C120.1 L8.1 R63.2 U16.11(VR)
GND: C118.2 C120.2 C121.2 C122.1 C123.2 C124.1 C125.1 C126.2 C128.2 C129.2 C130.1 C131.2 C132.1 C133.1 C134.2 C135.2 C136.2 C137.2 C138.2 C139.2 C140.2 C190.2 C191.2 C227.2 C228.2 C229.2 C230.2 C231.2 C232.2 C233.2 C234.2 C235.2 C236.2 C237.2 C238.2 C239.2 C240.2 C241.2 C242.2 C243.2 C244.2 C245.2 C246.2 C247.2 C248.2 C249.2 C250.2 C251.2 C252.2 C253.2 C254.2 C255.2 C256.2 C257.2 C258.2 C259.2 C260.2 C261.2 C262.2 C263.2 C264.2 C265.2 C266.2 C267.2 C268.2 C269.2 C270.2 C271.2 C272.2 C273.2 C274.2 C275.2 C276.2 C277.2 C278.2 C279.2 C280.2 C281.2 C282.2 C283.2 C284.2 C285.2 C286.2 C287.2 C288.2 C289.2 C290.2 C291.2 C292.2 C293.2 C294.2 C295.2 C296.2 C297.2 C298.2 C299.2 C300.2 C301.2 C302.2 C303.2 C304.2 C305.2 C306.2 C307.2 C308.2 C309.2 C310.2 C311.2 C312.2 D4.A(ANODE) D5.A(ANODE) D6.A(ANODE) D7.A(ANODE) D8.A(ANODE) D9.2(ANODE) D10.2(ANODE) DS2.C(CATHODE) J1.6 J2.1 J2.4 J5.11 J5.12 JP1.2 JP2.1 JP3.1 M1.1(G) M2.1(G) M3.1(G) M4.1(G) M5.1(G) M6.1(G) M7.1(G) M8.1(G) M9.1(G) M10.1(G) M11.1(G) M12.1(G) M13.1(G) M14.1(G) M15.1(G) M16.1(G) M17.1(G) M18.1(G) M19.1(G) M20.1(G) M21.1(G) M22.1(G) Q4.S(SOURCE) Q17.3(SOURCE) R114.2 R118.2 R121.2 R122.1 R125.1 R126.2 R131.2 R133.2 R135.2 R136.1 R138.1 R139.2 R168.1 R174.1 R176.1 R177.1 R181.1 R187.1 R189.1 R190.1 U16.6(NC6) U16.7(NC7) U16.8(NC8) U16.9(NC9) U16.10(NC10) U16.12(NC12) U16.13(NC13) U16.14(NC14) U16.16(NC16) U16.G0(GND) U17.6(NC6) U17.7(NC7) U17.8(NC8) U17.9(NC9) U17.10(NC10) U17.12(NC12) U17.13(NC13) U17.14(NC14) U17.16(NC16) U17.G0(GND) U18.3(GND1) U18.6(GND2) U24.3(PSG) U24.4(CG1) U24.5(CG2) U24.6(CG3) U34.2(GND_0) U34.3(GND_1) U34.7(AGND) U35.2(GND_0) U35.3(GND_1) U35.7(AGND) U36.3(PGND1) U36.8(PGND2) U36.9(PGND3) U36.12(AGND1) U36.13(AGND2) U36.19(PGND4) U36.20(PGND5) U36.23(PAD_GND) U37.3(PGND1) U37.8(PGND2) U37.9(PGND3) U37.12(AGND1) U37.13(AGND2) U37.19(PGND4) U37.20(PGND5) U37.23(PAD_GND) U38.3(PGND1) U38.8(PGND2) U38.9(PGND3) U38.12(AGND1) U38.13(AGND2) U38.19(PGND4) U38.20(PGND5) U38.23(PAD_GND) U39.6(E_B) U39.7(VEE) U39.8(GND) U40.9(DGND1) U40.34(DGND2) U40.55(DGND3) U40.60(AGND1) U40.61(AGND2) U40.63(EAN1) U40.65(EAN2) U40.67(EAN3) U40.69(EAN4) U40.73(CS-4B) U40.74(CS-3B) U40.78(CS-2B) U40.79(CS-1B) U40.80(AGND3) U41.6(E_B) U41.7(VEE) U41.8(GND) U42.9(DGND1) U42.34(DGND2) U42.55(DGND3) U42.60(AGND1) U42.61(AGND2) U42.63(EAN1) U42.65(EAN2) U42.67(EAN3) U42.69(EAN4) U42.73(CS-4B) U42.74(CS-3B) U42.78(CS-2B) U42.79(CS-1B) U42.80(AGND3) U43.4(VSS) U43.9(CENTERPAD) ; also on sheet 2 3 4 5 6 8 9 10 11 12 13 14 25 26 27
POWER1/DCDC1/V12D020W: C237.1 C238.1 L16.2 U35.1(VI) U35.12(VBIAS)
POWER1/DCDC2/V12D210W: C244.1 C245.1 L17.2 U36.1(VIN1) U36.2(VIN2)
POWER1/DCDC5/V12D210W: C253.1 C254.1 L18.2 U37.1(VIN1) U37.2(VIN2)
POWER1/DCDC6/V12D210W: C262.1 C263.1 L19.2 U38.1(VIN1) U38.2(VIN2)
POWER1/DCDC8/V12D010W: C230.1 C231.1 L15.2 U34.1(VI) U34.12(VBIAS)
POWER1/PWR1/V12PWRCTRL: C268.1 C271.1 L20.2 Q5.2(COLLECTOR) R166.1 R167.1
POWER1/PWR1/VCC3V3A_PWRCTL: C274.1 C275.1 C277.1 L21.2 U39.16(VCC) U40.58(V33A)
POWER1/PWR2/V12PWRCTRL: C290.1 C293.1 L22.2 Q6.2(COLLECTOR) R179.1 R180.1
POWER1/PWR2/VCC3V3_PWRCTL: C292.1 C294.1 C295.1 L23.1 Q6.3(EMITTER) R182.1 R185.1 R186.1 U42.8(V33DIO1) U42.56(V33DIO2) U42.57(V33D)
POWER1/PWR2/VCC3V3A_PWRCTL: C296.1 C297.1 C299.1 L23.2 U41.16(VCC) U42.58(V33A)
POWER1/VCC12_P_IN: C190.1 J2.3 J2.6 U24.1(B)
VCC1V8_ADC: C136.1 C140.1 R442.2 U18.4(Vout) ; also on sheet 3 4 5 6 9
VCC3V3: C248.1 C249.1 R119.1 R127.1 R128.1 R431.1 U36.10(VO_B1) U36.11(VO_B2) ; also on sheet 2 9 11 12 13 14 27
VCC3V3_DRV: C129.1 L10.2 ; also on sheet 26
VCC3V3_SYN: C121.1 L8.2 ; also on sheet 26
VCC5V0: L7.1 L9.1 R62.2 R64.2 R65.2 ; also on sheet 8 14 25 27
VCC12_P: C191.1 C227.1 C228.1 C229.1 C234.1 C235.1 C236.1 C241.1 C242.1 C243.1 C250.1 C251.1 C252.1 C259.1 C260.1 C261.1 C269.1 C291.1 D14.1(CATHODE) J61.2 L15.1 L16.1 L17.1 L18.1 L19.1 L20.1 L22.1 R407.1 R408.1 U24.2(CB) ; also on sheet 8
VCC_SPI: C312.1 U43.8(VCC) ; also on sheet 8
VCCAUX: C246.1 C247.1 D5.C(CATHODE) R117.1 U36.21(VO_A1) U36.22(VO_A2) ; also on sheet 9 27
VCCAUXMGT: C232.1 C233.1 R123.1 U34.4(VO) ; also on sheet 9
VCCBRAM: C257.1 C258.1 D6.C(CATHODE) R132.1 U37.10(VO_B1) U37.11(VO_B2) ; also on sheet 9
VCCINT: C239.1 C240.1 D4.C(CATHODE) R111.1 U35.4(VO) ; also on sheet 9
VCCMGTA: C264.1 C265.1 D7.C(CATHODE) R134.1 U38.21(VO_A1) U38.22(VO_A2) ; also on sheet 9 10
ADCREG/SENSE_1V8_ADC: R442.1 U18.5(SE)
ADCREG/SENSE_3V3_DRV: C127.1 R66.1 U17.2(RD)
ADCREG/SENSE_3V3_SYN: C119.1 R63.1 U16.2(RD)
FLASH_D0: J5.4 R197.1 ; also on sheet 25
FLASH_D1: J5.6 R198.1 ; also on sheet 25
FLASH_D2: J5.8 R199.1 ; also on sheet 25
FLASH_D3: J5.10 R200.1 ; also on sheet 25
POWER1/PWR1/TEMP: C279.1 U39.3(A) U40.7(TEMP)
POWER1/PWR1/TMUX0: U39.11(S0) U40.39(TMUX0)
POWER1/PWR1/TMUX1: U39.10(S1) U40.40(TMUX1)
POWER1/PWR1/TMUX2: U39.9(S2) U40.54(TMUX2)
POWER1/PWR2/TEMP: C301.1 U41.3(A) U42.7(TEMP)
POWER1/PWR2/TMUX0: U41.11(S0) U42.39(TMUX0)
POWER1/PWR2/TMUX1: U41.10(S1) U42.40(TMUX1)
POWER1/PWR2/TMUX2: U41.9(S2) U42.54(TMUX2)
POWER1/PWR_INH_B: JP1.1 R109.2 U34.8(INH_B) U35.8(INH_B)
POWER1/PWRCTL_PWRGOOD: Q4.G(GATE) R128.2 U40.49(PGOOD) U42.49(PGOOD)
POWER1/PWRCTL_SEQ_1: U40.32(SEQ-1) U42.32(SEQ-1)
POWER1/PWRCTL_SEQ_2: U40.53(SEQ-2) U42.53(SEQ-2)
POWER1/PWRCTL_SRE_GPIO1: U40.11(SRE-1B) U42.11(SRE-1B)
POWER1/PWRCTL_SRE_GPIO2: U40.37(SRE-2B) U42.37(SRE-2B)
POWER1/PWRCTL_SRE_GPIO3: U40.52(SRE-3B) U42.52(SRE-3B)
POWER1/PWRCTL_SRE_GPIO4: U40.50(SRE4B) U42.50(SRE4B)
POWER1/SENSE_2V5: C300.1 R130.2 R131.1 U42.62(EAP1)
POWER1/SENSE_3V3: C283.1 R119.2 R121.1 U40.66(EAP3)
POWER1/SENSE_AUX: C281.1 R117.2 R118.1 U40.18(FAULT-2B) U40.64(EAP2)
POWER1/SENSE_AUXMGT: C288.1 R123.2 R126.1 U40.68(EAP4)
POWER1/SENSE_BRAM: C303.1 R132.2 R133.1 U42.18(FAULT-2B) U42.64(EAP2)
POWER1/SENSE_INT: C278.1 R111.2 R114.1 U40.62(EAP1)
POWER1/SENSE_VCCMGTA: C305.1 R134.2 R135.1 U42.66(EAP3)
POWER1/SENSE_VTTMGTA: C310.1 R137.2 R139.1 U42.68(EAP4)
POWER1/VFAN: D14.2(ANODE) J61.1 Q17.2(DRAIN1) Q17.4(DRAIN2)
VADJ: C134.1 C135.1 C255.1 C256.1 J5.1 J5.2 L11.1 L12.1 R61.2 R130.1 R192.1 R193.1 R194.1 R195.1 R196.1 U37.21(VO_A1) U37.22(VO_A2) ; also on sheet 2 9 10 11 12 13 14 25 27
VTTMGTA: C266.1 C267.1 D8.C(CATHODE) R137.1 U38.10(VO_B1) U38.11(VO_B2) ; also on sheet 9
ADCREG/N190089: R62.1 U16.5(HV)
ADCREG/N190121: R64.1 U17.5(HV)
ADCREG/N190361: C122.2 U16.3(REF)
ADCREG/N190409: C124.2 C125.2 U16.4(VRX)
ADCREG/N190601: C127.2 C128.1 L10.1 R66.2 U17.11(VR)
ADCREG/N190787: C130.2 U17.3(REF)
ADCREG/N190815: R65.1 U17.1(EN)
ADCREG/N190831: C132.2 C133.2 U17.4(VRX)
ADCREG/N191211: R67.2 U18.1(SD)
FPGA14/N9860899: R192.2 R197.2 U43.5(DQ0)
FPGA14/N9860911: R193.2 R198.2 U43.2(DQ1)
FPGA14/N9860923: R194.2 R199.2 U43.3(DQ2_VPP_WP_B)
FPGA14/N9860930: R195.2 R200.2 U43.7(DQ3_HOLD_B)
N9912452: J5.9 ; also on sheet 2 25
N9912822: J5.3 U43.6(C) ; also on sheet 2
N9912826: J5.5 R196.2 U43.1(S_B) ; also on sheet 2
N9962816: R61.1 U16.1(EN) ; also on sheet 25
N9967310: J1.10 R115.2 U40.20(PMBUS_DATA) U42.20(PMBUS_DATA) ; also on sheet 3 25
N9967323: J1.9 R113.2 U40.19(PMBUS_CLK) U42.19(PMBUS_CLK) ; also on sheet 3 25
N9967336: J1.8 R112.2 U40.35(PMBUS_ALERT) U42.35(PMBUS_ALERT) ; also on sheet 3 25
N9967512: J1.7 R110.2 U40.36(PMBUS_CTRL) U42.36(PMBUS_CTRL) ; also on sheet 25
N9998463: Q17.1(GATE) R431.2 ; also on sheet 25
POWER1/N9950688: R122.2 U40.77(ADDR-0)
POWER1/N9950692: R125.2 U40.76(ADDR-1)
POWER1/N9953338: C270.1 C272.1 C273.1 L21.1 Q5.3(EMITTER) R109.1 R110.1 R112.1 R113.1 R115.1 R169.1 R172.1 R173.1 U40.8(V33DIO1) U40.56(V33DIO2) U40.57(V33D)
POWER1/N9957217: U35.11(PWM) U40.21(DPWM-1A)
POWER1/N9957233: U35.10(SRE) U40.12(SRE-1A)
POWER1/N9957245: U35.9(FAULT) U40.15(FAULT-1A)
POWER1/N9957257: U35.5(TEMP) U39.13(A0)
POWER1/N9961675: U36.18(PWM_A) U40.23(DPWM-2A)
POWER1/N9961687: U36.17(SRE_A) U40.51(SRE-2A)
POWER1/N9961716: U36.4(PWM_B) U40.25(DPWM-3A)
POWER1/N9961728: U36.5(SRE_B) U40.38(SRE-3A)
POWER1/N9961756: U36.15(FF_A) U40.17(FAULT-2A)
POWER1/N9961785: U36.7(FF_B) U40.29(FAULT-3A)
POWER1/N9961809: U36.16(TSENSE) U39.14(A1) U39.15(A2)
POWER1/N9964922: DS2.A(ANODE) R407.2 R408.2
POWER1/N9974756: DS1.A(ANODE) R127.2
POWER1/N9974764: DS1.C(CATHODE) Q4.D(DRAIN)
POWER1/N9976038: U37.18(PWM_A) U42.21(DPWM-1A)
POWER1/N9976042: U37.17(SRE_A) U42.12(SRE-1A)
POWER1/N9976046: U37.15(FF_A) U42.15(FAULT-1A)
POWER1/N9976050: U37.16(TSENSE) U41.13(A0) U41.14(A1)
POWER1/N9976204: U38.4(PWM_B) U42.27(DPWM-4A)
POWER1/N9976212: U38.7(FF_B) U42.42(FAULT-4A)
POWER1/N9976380: U37.4(PWM_B) U42.23(DPWM-2A)
POWER1/N9976384: U37.5(SRE_B) U42.51(SRE-2A)
POWER1/N9976388: U38.18(PWM_A) U42.25(DPWM-3A)
POWER1/N9976392: U38.17(SRE_A) U42.38(SRE-3A)
POWER1/N9976396: U37.7(FF_B) U42.17(FAULT-2A)
POWER1/N9976400: U38.15(FF_A) U42.29(FAULT-3A)
POWER1/N9976678: R136.2 U42.77(ADDR-0)
POWER1/N9976682: R138.2 U42.76(ADDR-1)
POWER1/N9979651: U38.16(TSENSE) U41.12(A3) U41.15(A2)
POWER1/N9981203: U34.11(PWM) U40.27(DPWM-4A)
POWER1/N9981207: U34.10(SRE) U40.33(SRE-4A)
POWER1/N9981215: U34.9(FAULT) U40.42(FAULT-4A)
POWER1/N9981383: U34.5(TEMP) U39.12(A3)
POWER1/N10023674: R170.1 TP5.1 U35.6(IOUT)
POWER1/N10023686: R171.1 TP7.1 U36.14(ISENSE_A)
POWER1/N10023698: R175.1 TP6.1 U36.6(ISENSE_B)
POWER1/N10024540: R183.1 TP9.1 U37.14(ISENSE_A)
POWER1/N10024867: R184.1 TP8.1 U37.6(ISENSE_B)
POWER1/N10025114: R188.1 TP11.1 U38.14(ISENSE_A)
POWER1/N10025413: R191.1 TP10.1 U38.6(ISENSE_B)
POWER1/N10026393: R178.1 TP4.1 U34.6(IOUT)
POWER1/N10027193: U38.5(SRE_B) U42.33(SRE-4A)
POWER1/PWR1/N9949306: R176.2 U40.72(AUX-IN_AD14)
POWER1/PWR1/N9949314: R177.2 U40.71(AUX-IN_AD13)
POWER1/PWR1/N9949358: C285.1 U40.1(ADC_REF)
POWER1/PWR1/N9949382: C286.1 C287.1 U40.59(BPCAP)
POWER1/PWR1/N9949868: C276.1 D9.1(CATHODE) Q5.1(BASE) R166.2 U40.70(V33FB)
POWER1/PWR1/N9950416: R173.2 U40.46(TDI)
POWER1/PWR1/N9950486: R172.2 U40.47(TMS)
POWER1/PWR1/N9950526: JP2.2 R169.2 U40.13(RESET_B)
POWER1/PWR1/N9950852: R167.2 R168.2 U40.5(VIN_IIN)
POWER1/PWR1/N9950942: R174.2 U40.48(TRST_B)
POWER1/PWR1/N9966024: C280.1 R170.2 U40.75(CS-1A)
POWER1/PWR1/N9968751: C289.1 R178.2 U40.2(CS-4A)
POWER1/PWR1/N9968995: C284.1 R175.2 U40.3(CS-3A)
POWER1/PWR1/N9969528: C282.1 R171.2 U40.4(CS-2A)
POWER1/PWR2/N9949306: R189.2 U42.72(AUX-IN_AD14)
POWER1/PWR2/N9949314: R190.2 U42.71(AUX-IN_AD13)
POWER1/PWR2/N9949358: C307.1 U42.1(ADC_REF)
POWER1/PWR2/N9949382: C308.1 C309.1 U42.59(BPCAP)
POWER1/PWR2/N9949868: C298.1 D10.1(CATHODE) Q6.1(BASE) R179.2 U42.70(V33FB)
POWER1/PWR2/N9950416: R186.2 U42.46(TDI)
POWER1/PWR2/N9950486: R185.2 U42.47(TMS)
POWER1/PWR2/N9950526: JP3.2 R182.2 U42.13(RESET_B)
POWER1/PWR2/N9950852: R180.2 R181.2 U42.5(VIN_IIN)
POWER1/PWR2/N9950942: R187.2 U42.48(TRST_B)
POWER1/PWR2/N9966024: C302.1 R183.2 U42.75(CS-1A)
POWER1/PWR2/N9968751: C311.1 R191.2 U42.2(CS-4A)
POWER1/PWR2/N9968995: C306.1 R188.2 U42.3(CS-3A)
POWER1/PWR2/N9969528: C304.1 R184.2 U42.4(CS-2A)

Not connected (* = marked no-connect by the designer): J1 1* 2* 3* 4* 5*; J2 2* 5*; J5 7*; U39 1(A4)* 2(A6)* 4(A7)* 5(A5)*; U40 6(VTRACK)* 10(SEQ-3)* 14(TRCK)* 16(FAULT-1B)* 22(DPWM-1B)* 24(DPWM-2B)* 26(DPWM-3B)* 28(DPWM-4B)* 30(SYNC-OUT)* 31(SYNC-IN)* 41(FAULT-3B)* 43(FAULT-4B)* 44(TCK)* 45(TDO)*; U41 1(A4)* 2(A6)* 4(A7)* 5(A5)*; U42 6(VTRACK)* 10(SEQ-3)* 14(TRCK)* 16(FAULT-1B)* 22(DPWM-1B)* 24(DPWM-2B)* 26(DPWM-3B)* 28(DPWM-4B)* 30(SYNC-OUT)* 31(SYNC-IN)* 41(FAULT-3B)* 43(FAULT-4B)* 44(TCK)* 45(TDO)*

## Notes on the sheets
sheet 15
- VCCAUX_IO should be connected
  to VCCAUX in all cases except
  when needing to run at the
  highest DDR3 line rates when
  it should be connected to
  2.0V.
- Contains U35 in Sheet 17
- Contains U40 in Sheet 21
- Internal FPGA Voltage 1.0 Volts
- POWER CONTROLLER 1
- KC705 SHEET 37 VCCINT
- KC705 SHEET 36
- 3.9V 320MA
- >1.5V 787 Ohms
- Keyed PMBUS Conn.
- <=1.5V DNP
- HDR_BOX_2X5
- Contains U36 in Sheet 18
- Digikey HRP10H-ND
- FPGA Aux Voltage 1.80 V
- 3.9V 320MA
- KC705 SHEET 38 VCCAUX
- >1.5V 787 Ohms
- <=1.5V DNP
- Used for JTAG, CLK
  GEN for ADCs
- KC705 SHEET 38 VCC3V3
- PMBUS Addr = 52
- KC705 SHEET 45
- Contains U34 in Sheet 16
- VCCAUXMGT 1.8V
- KC705 SHEET 35
- Use VCC1V8_ADC, since goes to bank 32
  which has VCCO = VCC1V8_ADC
- 2 x 1/10W for power dissipation
- MOLEX CONNECTOR
- Filter Digikey
  490-5055-ND
- Green LED
- Contains U42 in Sheet 22
- Contains U37 in Sheet 19
- KC705 SHEET 39 VADJ
- 12V CARD POWER INPUT
- POWER CONTROLLER 2
- KC705 SHEET 41
- Digikey WM1353-ND
- KC705 SHEET 40
- Used for VCCO of banks
  12,13,16 (ZDOK).
  Probably 3.3V
- Plug for Heatsink Fan
- Place near Xilinx
- Changed from VCC2V5 to VCC3V3 to
  match Xilinx in RevB
- >1.5V 787 Ohms
- 1.0V like VCCINT
- <=1.5V DNP
- KC705 SHEET 41 VCC1V5_FPGA
- 3.9V 320MA
- Contains U38 in Sheet 20
- >1.5V 787 Ohms
- KC705 SHEET 42
- <=1.5V DNP
- 1.0V like VCCINT if
  QPLL <=10.3125GHz
  else 1.05V
- 3.9V 320MA
- PMBUS Addr = 53
- VMGTAVTT 1.2V
- Green LED
- 3.9V 320MA
- MGT used in FPGA for driving SFP+ connectors
- KC705 SHEET 42 VTTMGTA
- See Kintex-7 FPGA Data Sheet : DC and AC Switching Characteristics
- This has the sequence for powering up the supplies.
- The recommended power-on sequence is VCCINT, VCCBRAM, VCCAUX, VCCAUX_IO, and VCCO to achieve minimum current
  draw and ensure that the I/Os are 3-stated at power-on. The recommended power-off sequence is the reverse of the poweron
  sequence. If VCCINT and VCCBRAM have the same recommended voltage levels then both can be powered by the same
  supply and ramped simultaneously. If VCCAUX, VCCAUX_IO, and VCCO have the same recommended voltage levels then they
  can be powered by the same supply and ramped simultaneously.
- The recommended GTX transceiver power-on sequence is VCCINT, VMGTAVCC, VMGTAVTT or VMGTAVCC,
  VCCINT, VMGTAVTT to achieve minimum current draw. There is no recommended sequencing for
  VMGTVCCAUX. Both VMGTAVCC and VCCINT can be ramped up simultaneously. The recommended power-off
  sequence is the reverse of the power-on sequence to achieve minimum current draw.
sheet 16
- 12V IN
- 0.7 TO 3.6 VOUT
- Dual 10 Amp Outputs
- 0.7 TO 3.6 VOUT
- KC705 Sheet 38
- Digikey
  PTD08D210WACT-ND
  not in stock
- Voltage out proportional to current delivered.
- Voltage out proportional to current delivered.
- I =( V-0.3)/0.2  I from 3 A to 10 A
- 10A gives 2.3V
sheet 17
- 12V IN
- 0.7 TO 3.6 VOUT
- 20A Max
- KC705 Sheet 37
- Digikey 296-23227-ND in stock
- Voltage out proportional to current delivered.
- I =( V-0.6)/0.066
- 20A gives 1.92V
sheet 18
- 12V IN
- 0.7 TO 3.6 VOUT
- Dual 10 Amp Outputs
- 0.7 TO 3.6 VOUT
- KC705 Sheet 38
- Digikey
  PTD08D210WACT-ND
  not in stock
- Voltage out proportional to current delivered.
- Voltage out proportional to current delivered.
- I =( V-0.3)/0.2  I from 3 A to 10 A
- 10A gives 2.3V
sheet 19
- 12V IN
- 0.7 TO 3.6 VOUT
- 10A Max
- KC705 Sheet 37
- Digikey 296-23167-ND in stock
- Voltage out proportional to current delivered.
- I =( V-0.6)/0.1
- 10A gives 1.6V
sheet 20
- FCX491ACT-ND
- Sheet 36
- VCCINT can be
  0.9 or 1.0 V
  to trade off
  speed and
  power.
- Provide resistor to ground
  to specify PMBUS address.
- SEQ 1&2 Wire-ored
- Wire-or to LED.
- 296-25804-ND
sheet 21
- FCX491ACT-ND
- Sheet 36
- VCCINT can be
  0.9 or 1.0 V
  to trade off
  speed and
  power.
- Provide resistor to ground
  to specify PMBUS address.
- SEQ 1&2 Wire-ored
- Wire-or to LED.
- 296-25804-ND
sheet 22
- 12V IN
- 0.7 TO 3.6 VOUT
- Dual 10 Amp Outputs
- 0.7 TO 3.6 VOUT
- KC705 Sheet 38
- Digikey
  PTD08D210WACT-ND
  not in stock
- Voltage out proportional to current delivered.
- Voltage out proportional to current delivered.
- I =( V-0.3)/0.2  I from 3 A to 10 A
- 10A gives 2.3V
sheet 23
- The R61 pullup
  Voltage  needs
  to be from
  VADJ_FPGA so
  as not  to
  over-voltage
  the Xilinx
  input.
- From Xilinx
  High >= 2 V
  Low <= 0.8V
- See PCB layout section of data sheet
- I = 1.5 ma
- Low-noise 3.3-volt regulator for LMX2581 Synthesizer
- I = 1.5 ma
- Low-noise 3.3-volt regulator for HMC987 clock driver
- See PCB guide in
  LP3856 data sheet
- I = 10 ma
- Iout Max = 3A
- 1.8-volt regulator for ADCs and Xilinx banks to ADC
- rev 2014-1-29: Add a pull-up to the synthesizer regulator.
- rev 2014-1-3: change resistor value from  82K to 82.5K for HMC976s.
     Change connection to HV input of both HMC976s from pull up common with
     the EN input to a separate DNP resistor.
sheet 24
- See KC705 Sheet 26
- 2.8V
- See KC705 Sheet 4
- Serial Flash Memory for
  storing Xilinx
  personality.
- See xapp586 for details on using SPI flash
- See KC705 Sheet 26
- Changed from 128M to
  256M to allow for
  larger Xilinxs
- Digikey Part 557-1565-ND
- SPI EXTERNAL PROGRAMMING HEADER
